(* Logix 5000 project; controller Test vendor 1 type 14 code 92 rev 33.11; software revision 33.00 *)

TASK MainTask (continuous, watchdog 500 ms) : MainProgram

MODULES
   Local : vendor 1 type 14 code 92 (ICP 0, rev 33.11)
      IN : vendor 1 type 7 code 1 (ICP 3, rev 3.2, Input RPI 20 ms)
      O : vendor 1 type 7 code 15 (ICP 2, rev 3.2, Output RPI 20 ms)
      Ethernet : 1756-ENBT (ICP 1, Ethernet 192.168.0.98, rev 6.4)
         IOLM1 : DXM (Ethernet 192.168.0.1, rev 2.22, StandardDataDriven RPI 20 ms)
END_MODULES

TYPE Banner_IOL_Device_SubIndex :
STRUCT
   Sub : DINT[34];
END_STRUCT
END_TYPE

TYPE Banner_IOL_Port_v5 :   // UDT that has all of the data items necessary to communicate with a specific Port on a IO-Link Master
STRUCT
   Port_Controlled : INT;   // Each bit represents a port on an IO-Link Master. Set to 1 to tell AOI to control that port.
   Port_Activate : INT;   // Each bit represents a port on an IO-Link Master. When ON that port will process any commands in queue.
   Port_Read : INT;   // Each bit represents a port on an IO-Link Master. Used to determine when device AOI has requested a Read command.
   Port_Write : INT;   // Each bit represents a port on an IO-Link Master. Used to determine when device AOI has requested a Write command.
   Port_RW_Complete : INT;   // Each bit represents a port on an IO-Link Master. Tells device AOI that Read or Write request has been completed.
   Port_Device_Read : INT;
   Data_Transfer : SINT[250];   // Array to transfer data from IO-Master to device AOIs.
END_STRUCT
END_TYPE

TYPE Banner_IOL_QM30VT3_Device :
STRUCT
   Initial_Global_Read : BOOL;
   Command : SINT;
   Data : Banner_IOL_QM30VT3_Device_Index;
   Reset : BOOL;
END_STRUCT
END_TYPE

TYPE Banner_IOL_QM30VT3_Device_Index :
STRUCT
   Index : Banner_IOL_Device_SubIndex[19];
   Metric_Config : Banner_IOL_QM30VT3_Metric_Config;
END_STRUCT
END_TYPE

TYPE Banner_IOL_QM30VT3_Metric_Config :
STRUCT
   Metric_1 : Banner_IOL_QM30VT3_Metric_Data;
   Metric_2 : Banner_IOL_QM30VT3_Metric_Data;
   Metric_3 : Banner_IOL_QM30VT3_Metric_Data;
   Metric_4 : Banner_IOL_QM30VT3_Metric_Data;
   Metric_5 : Banner_IOL_QM30VT3_Metric_Data;
   Metric_6 : Banner_IOL_QM30VT3_Metric_Data;
   Metric_7 : Banner_IOL_QM30VT3_Metric_Data;
   Num_of_Threshold_Samples : DINT;
END_STRUCT
END_TYPE

TYPE Banner_IOL_QM30VT3_Metric_Data :
STRUCT
   Metric : DINT;   // See IODD file for all options.
   Warning_Threshold : REAL;
   Alarm_Treshold : REAL;
END_STRUCT
END_TYPE

TYPE Banner_IOL_Rules :
STRUCT
   Byte_Pos : SINT;   // Byte Position to read from or write data to.
   Multi : SINT;   // Determines if a multiple byte length index is being accessed. Use 2 for 2 bytes length, 3 for 3 byte length, etc..
   Sub_Index : SINT;
   Signed : SINT;   // 0=Unsigned, 1=Signed
END_STRUCT
END_TYPE

TYPE Banner_IOL_Rules_Array :
STRUCT
   Length : DINT;
   Settings : Banner_IOL_Rules_SettingsArray[32];
END_STRUCT
END_TYPE

TYPE Banner_IOL_Rules_SettingsArray :
STRUCT
   Index : DINT;
   Num_Op : INT;   // Number of Operations to read/write Index.
   Total_Bytes : INT;
   RW : SINT;   // 0 = Read Only, 1 = Write Only, 2 = Read or Write
   Rules : Banner_IOL_Rules[34];   // Sub Index Position in IODD.
END_STRUCT
END_TYPE

TYPE Banner_IOLM_EL_v5 :   // Error Log for Messages to IOLM.
STRUCT
   RW : SINT;   // 0 = Read, 1 = Write.
   Port : SINT;   // Port number that generated error.
   Index : INT;   // IO-Link Index for generated error.
END_STRUCT
END_TYPE

TYPE Banner_IOLM_v5 :   // UDT to control IO-Link Masters.
STRUCT
   Message_Source_Data : SINT[260];
   Message_Destination_Data : SINT[260];
   Error_Log : Banner_IOLM_EL_v5[10];
   Error_Write_Retry : BOOL;
   Num_Error_MSGS : DINT;
   IO_Link_Master_Busy : BOOL;   // 0 = While waiting for a command, 1 = Processing command
   AOI_Reset : BOOL;
   Port_Data : Banner_IOL_Port_v5;   // All of the necessary data to work with the various ports of the IO-Link Master.
   Halt_Operation : BOOL;   // When parameter is 1 the AOI is halted as next available time frame.
   AOI_Halted : BOOL;   // AOI is in standby mode until Halt Operation tag is set back to 0.
END_STRUCT
END_TYPE

TYPE Banner_QM30VT3_FP_RMS_PD_v5 :
STRUCT
   X_RMS_Velocity : REAL;   // in/sec or mm/sec
   Y_RMS_Velocity : REAL;   // in/sec or mm/sec
   Z_RMS_Velocity : REAL;   // in/sec or mm/sec
   X_High_Freq_RMS_Accel : REAL;   // G
   Y_High_Freq_RMS_Accel : REAL;   // G
   Z_High_Freq_RMS_Accel : REAL;   // G
   Temperature : REAL;   // F or C
   X : Banner_QM30VT3_FP_RMS_XYZ_PD_v5;
   Y : Banner_QM30VT3_FP_RMS_XYZ_PD_v5;
   Z : Banner_QM30VT3_FP_RMS_XYZ_PD_v5;
   Temp_Warning : BOOL;
   Temp_Alarm : BOOL;
END_STRUCT
END_TYPE

TYPE Banner_QM30VT3_FP_RMS_XYZ_PD_v5 :
STRUCT
   Vel_Acute_Warning : BOOL;
   Vel_Acute_Alarm : BOOL;
   Vel_Chronic_Warning : BOOL;
   Vel_Chronic_Alarm : BOOL;
   HiFreq_Accel_Acute_Warning : BOOL;
   HiFreq_Accel_Acute_Alarm : BOOL;
   HiFreq_Accel_Chronic_Warning : BOOL;
   HiFreq_Accel_Chronic_Alarm : BOOL;
END_STRUCT
END_TYPE

TYPE Banner_QM30VT3_PDI_v5 :
STRUCT
   PD0_FP_imperial : Banner_QM30VT3_FP_RMS_PD_v5;
   PD1_SS_imperial : Banner_QM30VT3_SS_RMS_PD_v5;
   PD2_FP_metric : Banner_QM30VT3_FP_RMS_PD_v5;
   PD3_SS_metric : Banner_QM30VT3_SS_RMS_PD_v5;
   PD4_User_metric : Banner_QM30VT3_User_PD_v5;
   PD5_User_imperial : Banner_QM30VT3_User_PD_v5;
   DTI : SINT[32];
END_STRUCT
END_TYPE

TYPE Banner_QM30VT3_SS_RMS_PD_HiFreq_v5 :
STRUCT
   High_Frequency_RMS_Accel : DINT;
   Scale : INT;
   HiFreq_Accel_Acute_Warning : BOOL;
   HiFreq_Accel_Acute_Alarm : BOOL;
   HiFreq_Accel_Chronic_Warning : BOOL;
   HiFreq_Accel_Chronice_Alarm : BOOL;
END_STRUCT
END_TYPE

TYPE Banner_QM30VT3_SS_RMS_PD_v5 :
STRUCT
   X_Velocity : Banner_QM30VT3_SS_RMS_Vel_PD_v5;
   Y_Velocity : Banner_QM30VT3_SS_RMS_Vel_PD_v5;
   Z_Velocity : Banner_QM30VT3_SS_RMS_Vel_PD_v5;
   X_HiFreq : Banner_QM30VT3_SS_RMS_PD_HiFreq_v5;
   Y_HiFreq : Banner_QM30VT3_SS_RMS_PD_HiFreq_v5;
   Z_HiFreq : Banner_QM30VT3_SS_RMS_PD_HiFreq_v5;
   Temperature : DINT;   // F or C
   Scale : INT;
   Temp_Warning : BOOL;
   Temp_Alarm : BOOL;
END_STRUCT
END_TYPE

TYPE Banner_QM30VT3_SS_RMS_Vel_PD_v5 :
STRUCT
   RMS_Velocity : DINT;   // in/s or mm/sec
   Scale : INT;
   Vel_Acute_Warning : BOOL;
   Vel_Acute_Alarm : BOOL;
   Vel_Chronic_Warning : BOOL;
   Vel_Chronic_Alarm : BOOL;
END_STRUCT
END_TYPE

TYPE Banner_QM30VT3_User_PD_v5 :
STRUCT
   Metric : REAL[8];
   M1_Chan_1_Warning : BOOL;
   M1_Chan_2_Alarm : BOOL;
   M2_Chan_1_Warning : BOOL;
   M2_Chan_2_Alarm : BOOL;
   M3_Chan_1_Warning : BOOL;
   M3_Chan_2_Alarm : BOOL;
   M4_Chan_1_Warning : BOOL;
   M4_Chan_2_Alarm : BOOL;
   M5_Chan_1_Warning : BOOL;
   M5_Chan_2_Alarm : BOOL;
   M6_Chan_1_Warning : BOOL;
   M6_Chan_2_Alarm : BOOL;
   M7_Chan_1_Warning : BOOL;
   M7_Chan_2_Alarm : BOOL;
END_STRUCT
END_TYPE

ADD_ON_INSTRUCTION Banner_DXMR_IOLM_Param_v5   (* revision 5.0, vendor Banner Engineering *)
// AOI that controls a Banner IO-Link Master with IO-Link Devices
// Revision note:
// Added Port Control functionality. This should simplify the setup. Also added links for direct connection to the Input and Output Assmebly Instances.
VAR_IN_OUT
   IOLM : Banner_IOLM_v5; {required}
   Input : SINT[456]; {required}
   Output : SINT[456]; {required}
END_VAR
VAR_INPUT
   Port1 : BOOL; {required}
   Port2 : BOOL; {required}
   Port3 : BOOL; {required}
   Port4 : BOOL; {required}
   Port5 : BOOL; {required}
   Port6 : BOOL; {required}
   Port7 : BOOL; {required}
   Port8 : BOOL; {required}
END_VAR
VAR_OUTPUT
   Done : BOOL; {visible}
   Busy : BOOL; {visible}
   Error : BOOL; {visible}
END_VAR
VAR
   Lock : DINT; {access None}
   Byte_Length : SINT; {access None}
   Current_Port : INT; {access None}   // Current port to communicate with via the IO-Link Master.
   Timer : TIMER := (PRE := 500); {access None}
   Error_Index : DINT; {access None}
   Timer2 : TIMER := (PRE := 5000); {access None}
   Temp_Index : INT; {access None}
   ErrCount : DINT; {access None}
   Timer4 : TIMER := (PRE := 2000); {access None}
   Timer5 : TIMER := (PRE := 2000); {access None}
   Timer3 : TIMER := (PRE := 2000); {access None}
   Timer6 : TIMER := (PRE := 3000); {access None}
   Timer7 : TIMER := (PRE := 3000); {access None}
   Timer8 : TIMER := (PRE := 3000); {access None}
   Write_Index : DINT; {access None}
   WriteTimer : TIMER := (PRE := 60000); {access None}
   WriteCnt : DINT; {access None}
   Last_Index : DINT; {access None}
   WrCntTotal : DINT; {access None}
END_VAR

ROUTINE Logic   (* ladder *)
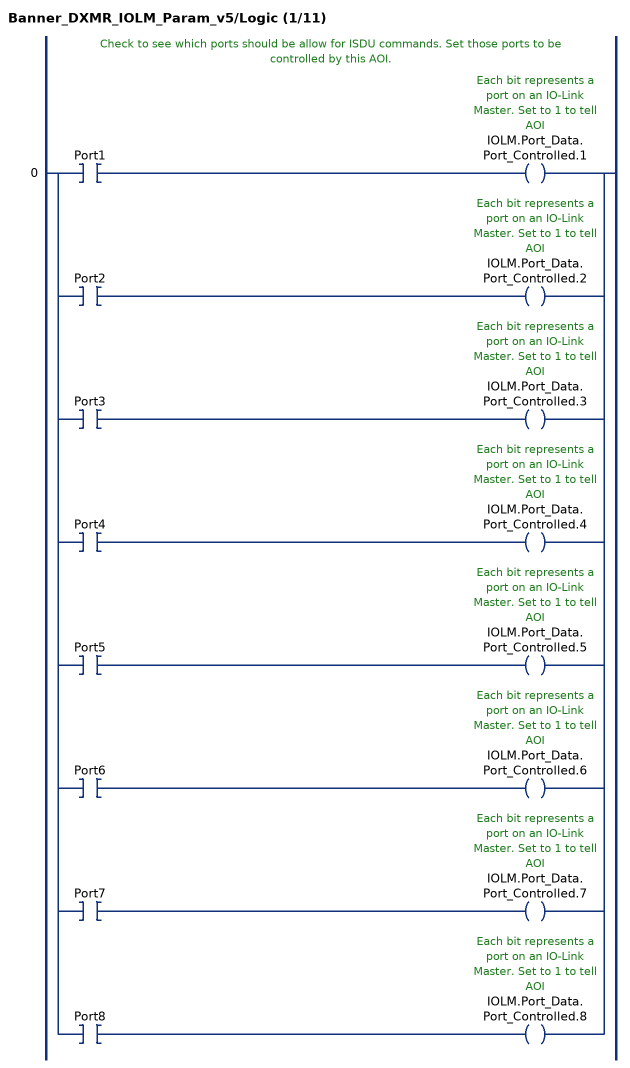
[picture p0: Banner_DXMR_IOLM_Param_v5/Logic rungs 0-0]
   // Check to see which ports should be allow for ISDU commands. Set those ports to be controlled by this AOI.
   0: [XIC(Port1) OTE(IOLM.Port_Data.Port_Controlled.1) ,XIC(Port2) OTE(IOLM.Port_Data.Port_Controlled.2) ,XIC(Port3) OTE(IOLM.Port_Data.Port_Controlled.3) ,XIC(Port4) OTE(IOLM.Port_Data.Port_Controlled.4) ,XIC(Port5) OTE(IOLM.Port_Data.Port_Controlled.5) ,XIC(Port6) OTE(IOLM.Port_Data.Port_Controlled.6) ,XIC(Port7) OTE(IOLM.Port_Data.Port_Controlled.7) ,XIC(Port8) OTE(IOLM.Port_Data.Port_Controlled.8) ];
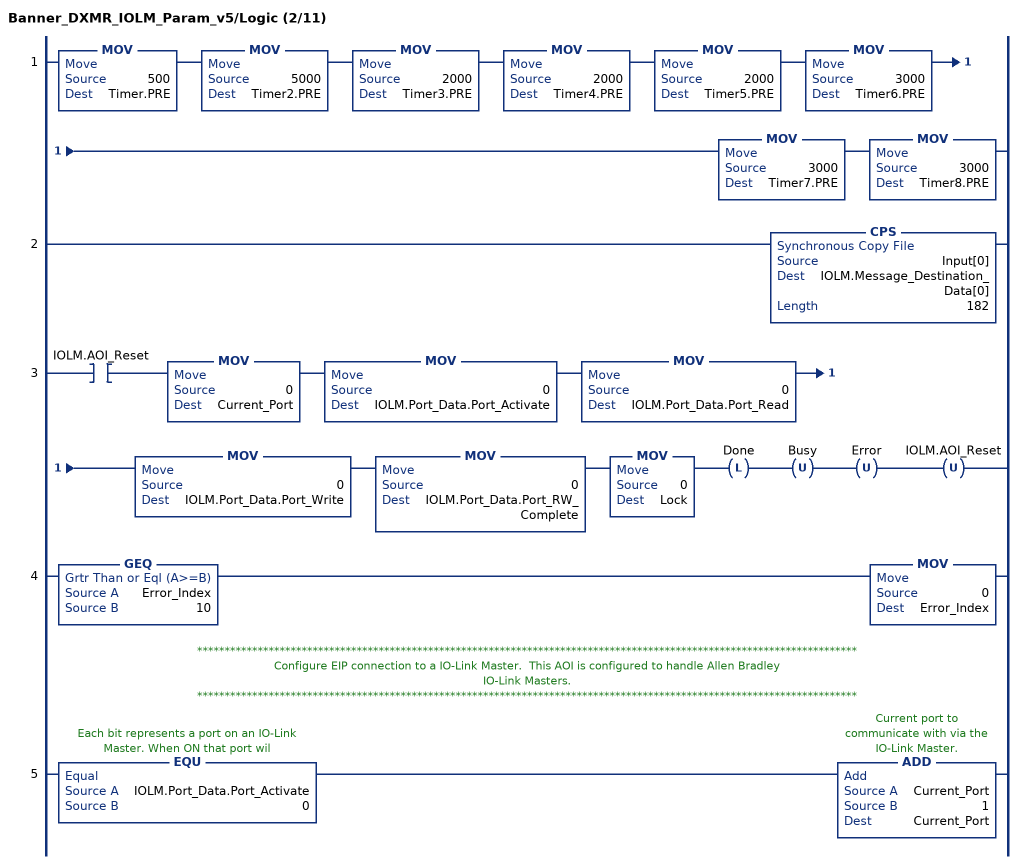
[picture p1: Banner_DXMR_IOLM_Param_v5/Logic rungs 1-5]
   1: MOV(500,Timer.PRE)MOV(5000,Timer2.PRE)MOV(2000,Timer3.PRE)MOV(2000,Timer4.PRE)MOV(2000,Timer5.PRE)MOV(3000,Timer6.PRE)MOV(3000,Timer7.PRE)MOV(3000,Timer8.PRE);
   2: CPS(Input[0],IOLM.Message_Destination_Data[0],182);
   3: XIC(IOLM.AOI_Reset)MOV(0,Current_Port)MOV(0,IOLM.Port_Data.Port_Activate)MOV(0,IOLM.Port_Data.Port_Read)MOV(0,IOLM.Port_Data.Port_Write)MOV(0,IOLM.Port_Data.Port_RW_Complete)MOV(0,Lock)OTL(Done)OTU(Busy)OTU(Error)OTU(IOLM.AOI_Reset);
   4: GEQ(Error_Index,10)MOV(0,Error_Index);
   // ************************************************************************************************************************
   // Configure EIP connection to a IO-Link Master.  This AOI is configured to handle Allen Bradley
   // IO-Link Masters.
   // ************************************************************************************************************************
   5: EQU(IOLM.Port_Data.Port_Activate,0)ADD(Current_Port,1,Current_Port);
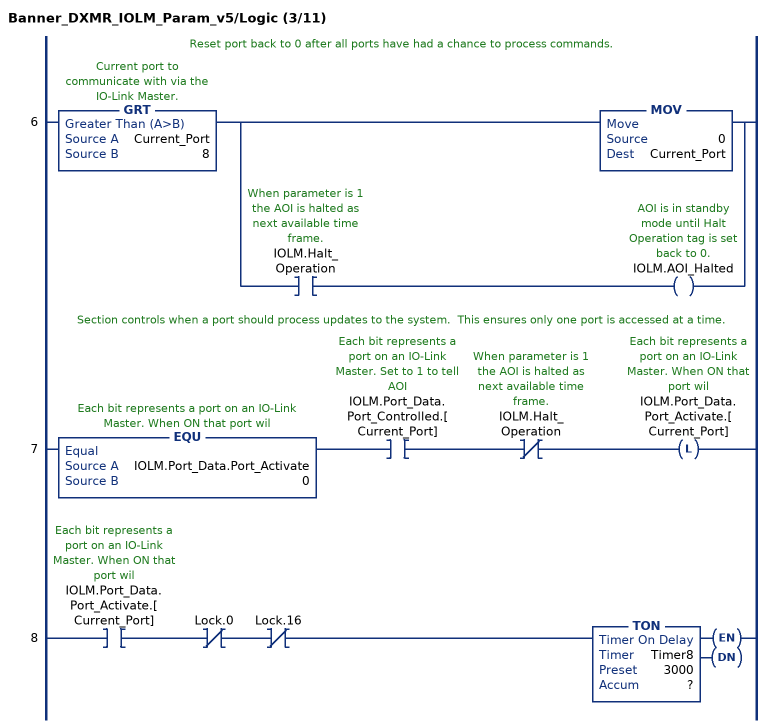
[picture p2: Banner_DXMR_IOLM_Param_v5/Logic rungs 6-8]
   // Reset port back to 0 after all ports have had a chance to process commands.
   6: GRT(Current_Port,8)[MOV(0,Current_Port) ,XIC(IOLM.Halt_Operation) OTE(IOLM.AOI_Halted) ];
   // Section controls when a port should process updates to the system.  This ensures only one port is accessed at a time.
   7: EQU(IOLM.Port_Data.Port_Activate,0)XIC(IOLM.Port_Data.Port_Controlled.[Current_Port])XIO(IOLM.Halt_Operation)OTL(IOLM.Port_Data.Port_Activate.[Current_Port]);
   8: XIC(IOLM.Port_Data.Port_Activate.[Current_Port])XIO(Lock.0)XIO(Lock.16)TON(Timer8,?,?);
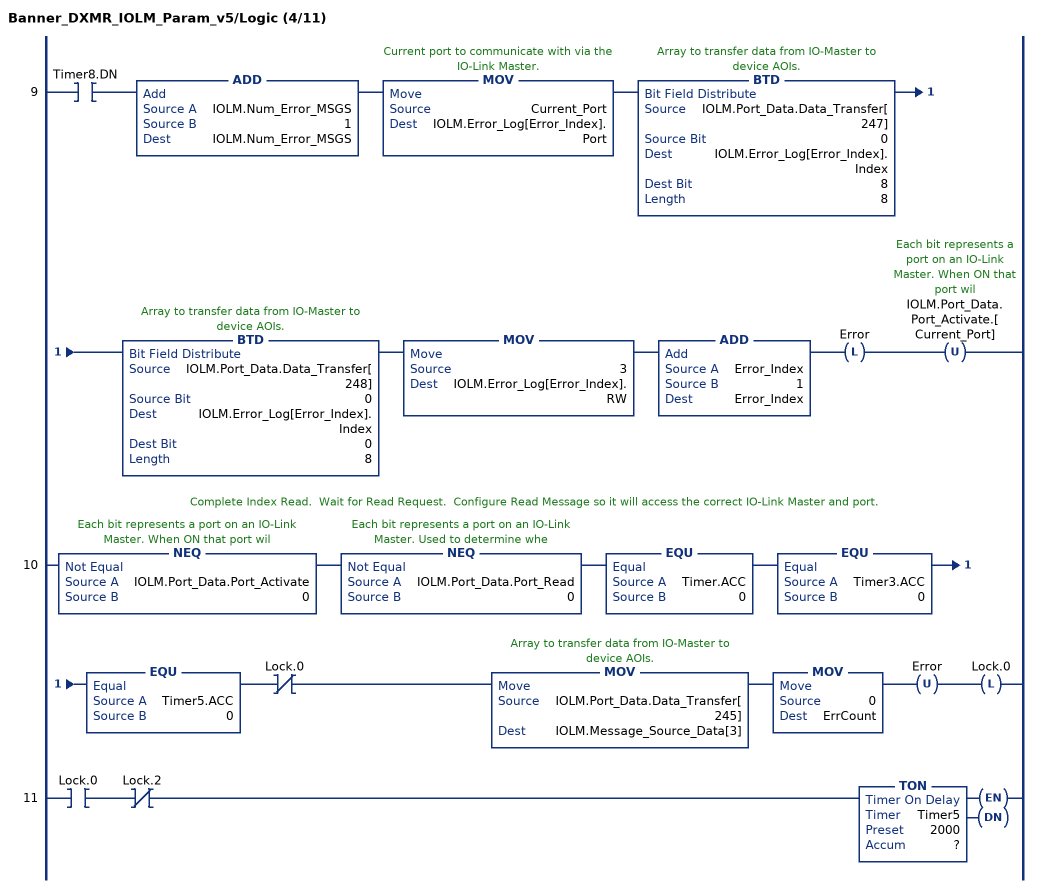
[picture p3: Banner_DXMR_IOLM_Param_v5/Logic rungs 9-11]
   9: XIC(Timer8.DN)ADD(IOLM.Num_Error_MSGS,1,IOLM.Num_Error_MSGS)MOV(Current_Port,IOLM.Error_Log[Error_Index].Port)BTD(IOLM.Port_Data.Data_Transfer[247],0,IOLM.Error_Log[Error_Index].Index,8,8)BTD(IOLM.Port_Data.Data_Transfer[248],0,IOLM.Error_Log[Error_Index].Index,0,8)MOV(3,IOLM.Error_Log[Error_Index].RW)ADD(Error_Index,1,Error_Index)OTL(Error)OTU(IOLM.Port_Data.Port_Activate.[Current_Port]);
   // Complete Index Read.  Wait for Read Request.  Configure Read Message so it will access the correct IO-Link Master and port.
   10: NEQ(IOLM.Port_Data.Port_Activate,0)NEQ(IOLM.Port_Data.Port_Read,0)EQU(Timer.ACC,0)EQU(Timer3.ACC,0)EQU(Timer5.ACC,0)XIO(Lock.0)MOV(IOLM.Port_Data.Data_Transfer[245],IOLM.Message_Source_Data[3])MOV(0,ErrCount)OTU(Error)OTL(Lock.0);
   11: XIC(Lock.0)XIO(Lock.2)TON(Timer5,?,?);
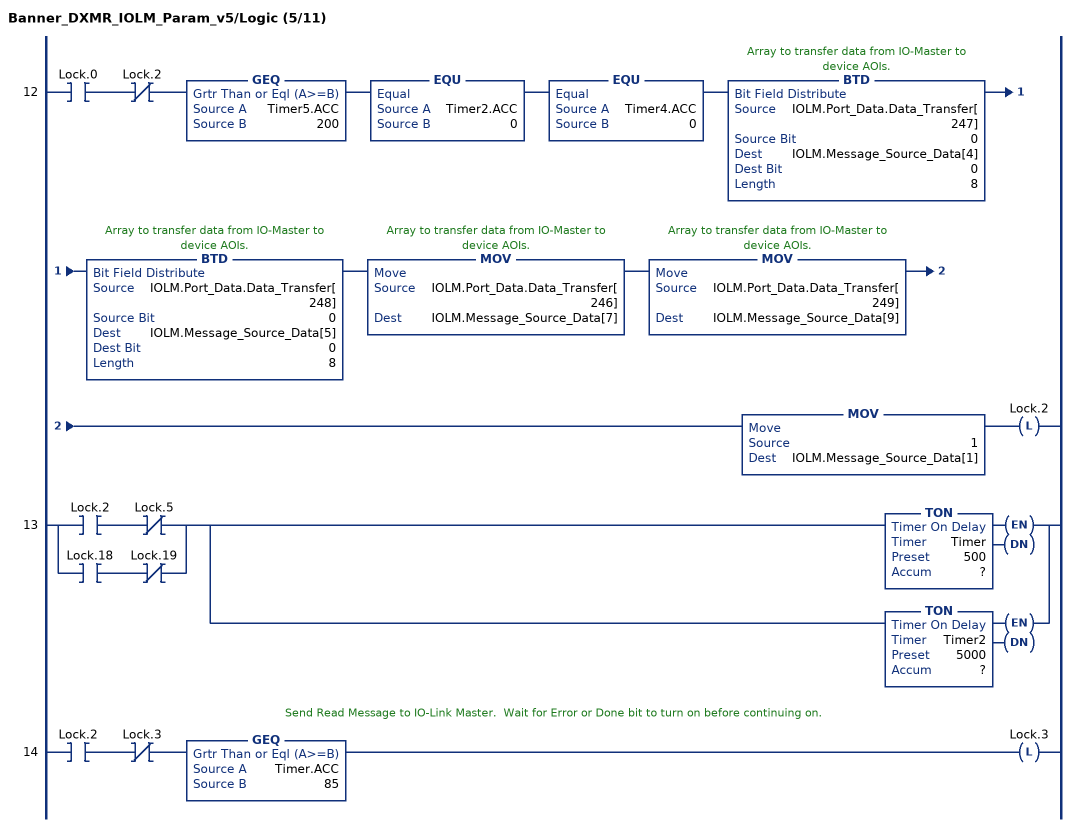
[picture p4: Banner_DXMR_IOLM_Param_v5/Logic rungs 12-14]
   12: XIC(Lock.0)XIO(Lock.2)GEQ(Timer5.ACC,200)EQU(Timer2.ACC,0)EQU(Timer4.ACC,0)BTD(IOLM.Port_Data.Data_Transfer[247],0,IOLM.Message_Source_Data[4],0,8)BTD(IOLM.Port_Data.Data_Transfer[248],0,IOLM.Message_Source_Data[5],0,8)MOV(IOLM.Port_Data.Data_Transfer[246],IOLM.Message_Source_Data[7])MOV(IOLM.Port_Data.Data_Transfer[249],IOLM.Message_Source_Data[9])MOV(1,IOLM.Message_Source_Data[1])OTL(Lock.2);
   13: [XIC(Lock.2) XIO(Lock.5) ,XIC(Lock.18) XIO(Lock.19) ][TON(Timer,?,?) ,TON(Timer2,?,?) ];
   // Send Read Message to IO-Link Master.  Wait for Error or Done bit to turn on before continuing on.
   14: XIC(Lock.2)XIO(Lock.3)GEQ(Timer.ACC,85)OTL(Lock.3);
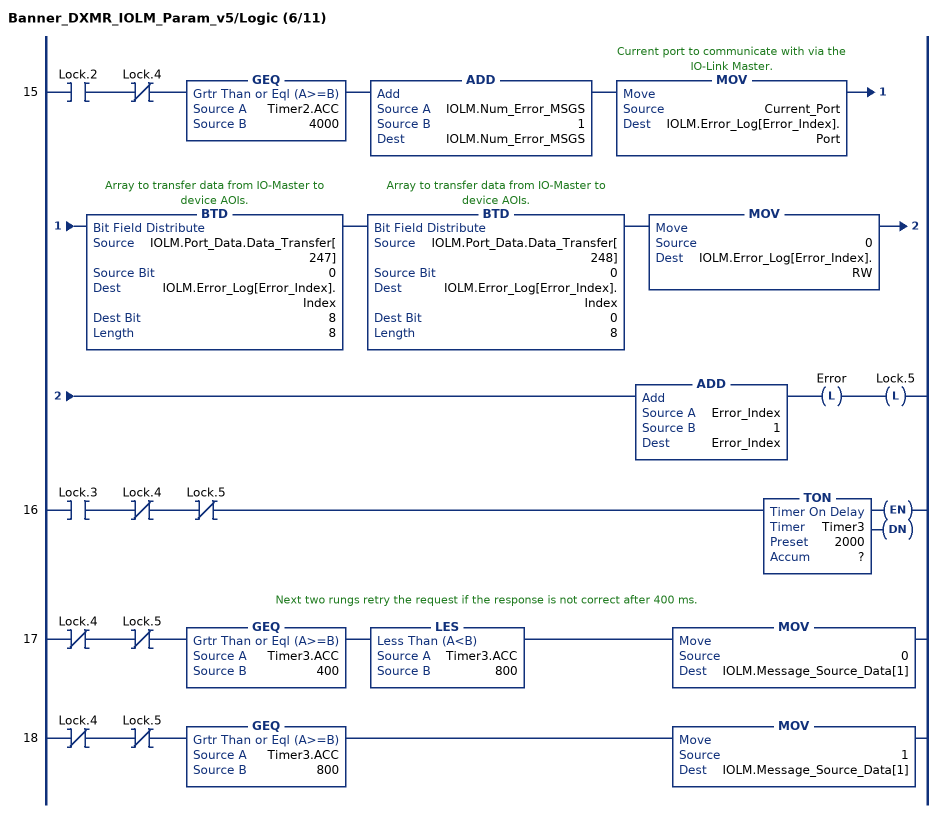
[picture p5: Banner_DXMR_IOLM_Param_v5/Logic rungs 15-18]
   15: XIC(Lock.2)XIO(Lock.4)GEQ(Timer2.ACC,4000)ADD(IOLM.Num_Error_MSGS,1,IOLM.Num_Error_MSGS)MOV(Current_Port,IOLM.Error_Log[Error_Index].Port)BTD(IOLM.Port_Data.Data_Transfer[247],0,IOLM.Error_Log[Error_Index].Index,8,8)BTD(IOLM.Port_Data.Data_Transfer[248],0,IOLM.Error_Log[Error_Index].Index,0,8)MOV(0,IOLM.Error_Log[Error_Index].RW)ADD(Error_Index,1,Error_Index)OTL(Error)OTL(Lock.5);
   16: XIC(Lock.3)XIO(Lock.4)XIO(Lock.5)TON(Timer3,?,?);
   // Next two rungs retry the request if the response is not correct after 400 ms.
   17: XIO(Lock.4)XIO(Lock.5)GEQ(Timer3.ACC,400)LES(Timer3.ACC,800)MOV(0,IOLM.Message_Source_Data[1]);
   18: XIO(Lock.4)XIO(Lock.5)GEQ(Timer3.ACC,800)MOV(1,IOLM.Message_Source_Data[1]);
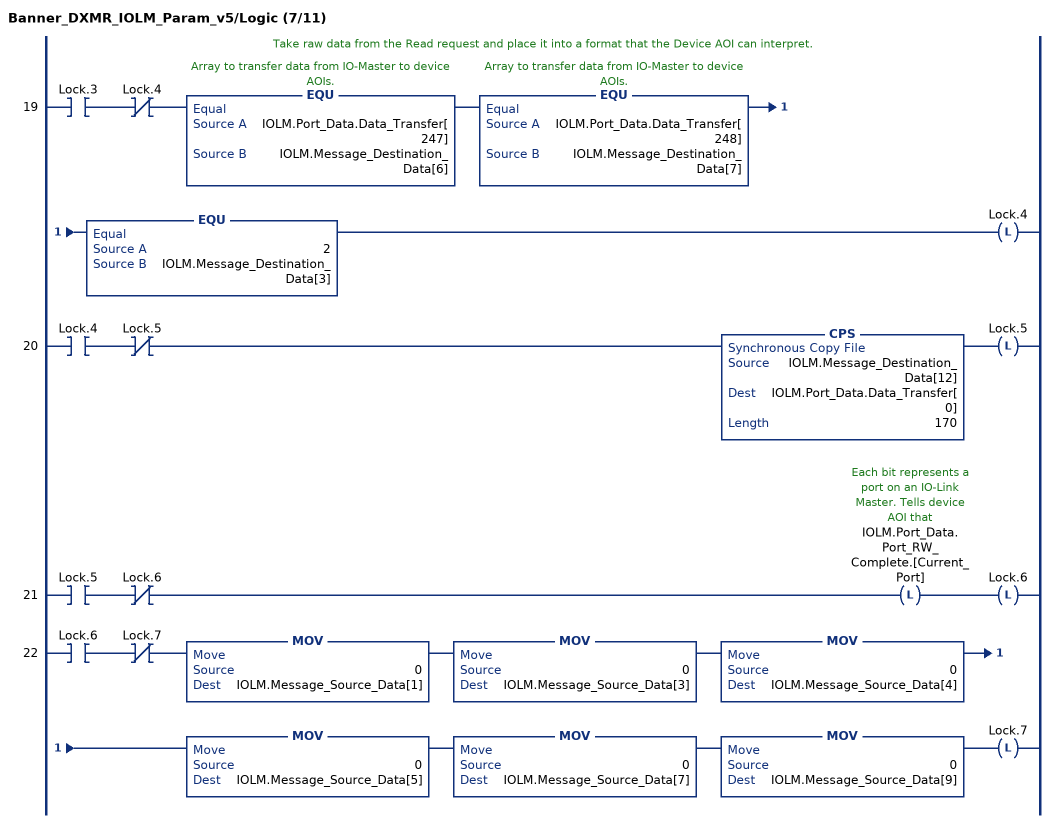
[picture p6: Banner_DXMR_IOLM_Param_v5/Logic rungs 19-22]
   // Take raw data from the Read request and place it into a format that the Device AOI can interpret.
   19: XIC(Lock.3)XIO(Lock.4)EQU(IOLM.Port_Data.Data_Transfer[247],IOLM.Message_Destination_Data[6])EQU(IOLM.Port_Data.Data_Transfer[248],IOLM.Message_Destination_Data[7])EQU(2,IOLM.Message_Destination_Data[3])OTL(Lock.4);
   20: XIC(Lock.4)XIO(Lock.5)CPS(IOLM.Message_Destination_Data[12],IOLM.Port_Data.Data_Transfer[0],170)OTL(Lock.5);
   21: XIC(Lock.5)XIO(Lock.6)OTL(IOLM.Port_Data.Port_RW_Complete.[Current_Port])OTL(Lock.6);
   22: XIC(Lock.6)XIO(Lock.7)MOV(0,IOLM.Message_Source_Data[1])MOV(0,IOLM.Message_Source_Data[3])MOV(0,IOLM.Message_Source_Data[4])MOV(0,IOLM.Message_Source_Data[5])MOV(0,IOLM.Message_Source_Data[7])MOV(0,IOLM.Message_Source_Data[9])OTL(Lock.7);
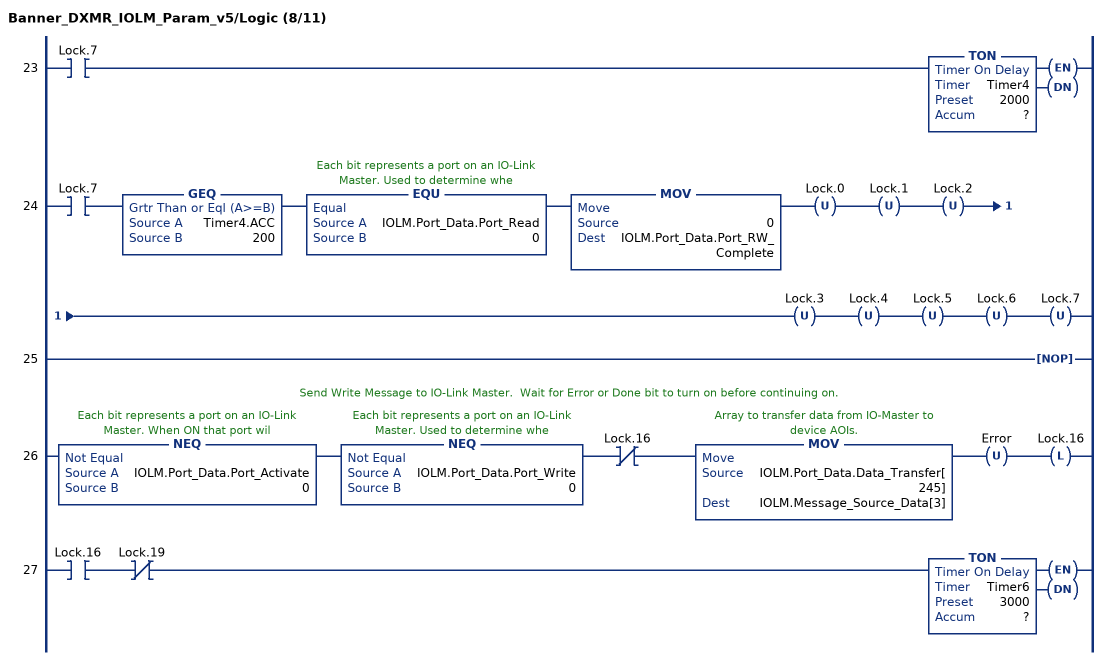
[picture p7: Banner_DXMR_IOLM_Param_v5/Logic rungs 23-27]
   23: XIC(Lock.7)TON(Timer4,?,?);
   24: XIC(Lock.7)GEQ(Timer4.ACC,200)EQU(IOLM.Port_Data.Port_Read,0)MOV(0,IOLM.Port_Data.Port_RW_Complete)OTU(Lock.0)OTU(Lock.1)OTU(Lock.2)OTU(Lock.3)OTU(Lock.4)OTU(Lock.5)OTU(Lock.6)OTU(Lock.7);
   25: NOP();
   // Send Write Message to IO-Link Master.  Wait for Error or Done bit to turn on before continuing on.
   26: NEQ(IOLM.Port_Data.Port_Activate,0)NEQ(IOLM.Port_Data.Port_Write,0)XIO(Lock.16)MOV(IOLM.Port_Data.Data_Transfer[245],IOLM.Message_Source_Data[3])OTU(Error)OTL(Lock.16);
   27: XIC(Lock.16)XIO(Lock.19)TON(Timer6,?,?);
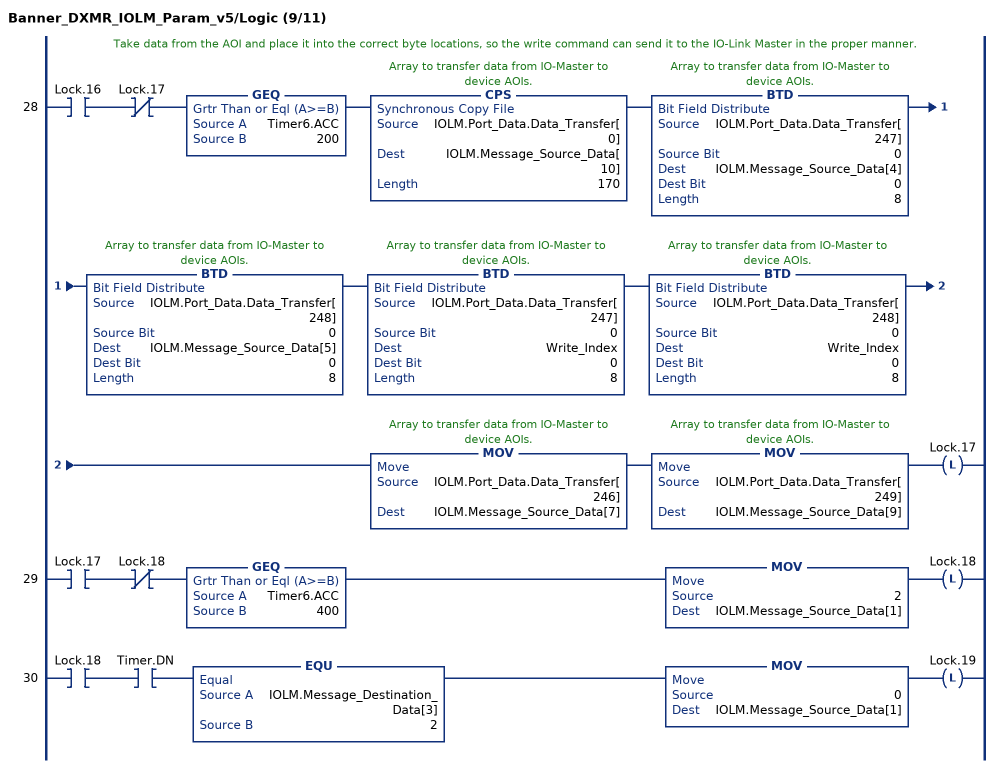
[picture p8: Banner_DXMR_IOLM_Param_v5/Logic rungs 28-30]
   // Take data from the AOI and place it into the correct byte locations, so the write command can send it to the IO-Link Master in the proper manner.
   28: XIC(Lock.16)XIO(Lock.17)GEQ(Timer6.ACC,200)CPS(IOLM.Port_Data.Data_Transfer[0],IOLM.Message_Source_Data[10],170)BTD(IOLM.Port_Data.Data_Transfer[247],0,IOLM.Message_Source_Data[4],0,8)BTD(IOLM.Port_Data.Data_Transfer[248],0,IOLM.Message_Source_Data[5],0,8)BTD(IOLM.Port_Data.Data_Transfer[247],0,Write_Index,0,8)BTD(IOLM.Port_Data.Data_Transfer[248],0,Write_Index,0,8)MOV(IOLM.Port_Data.Data_Transfer[246],IOLM.Message_Source_Data[7])MOV(IOLM.Port_Data.Data_Transfer[249],IOLM.Message_Source_Data[9])OTL(Lock.17);
   29: XIC(Lock.17)XIO(Lock.18)GEQ(Timer6.ACC,400)MOV(2,IOLM.Message_Source_Data[1])OTL(Lock.18);
   30: XIC(Lock.18)XIC(Timer.DN)EQU(IOLM.Message_Destination_Data[3],2)MOV(0,IOLM.Message_Source_Data[1])OTL(Lock.19);
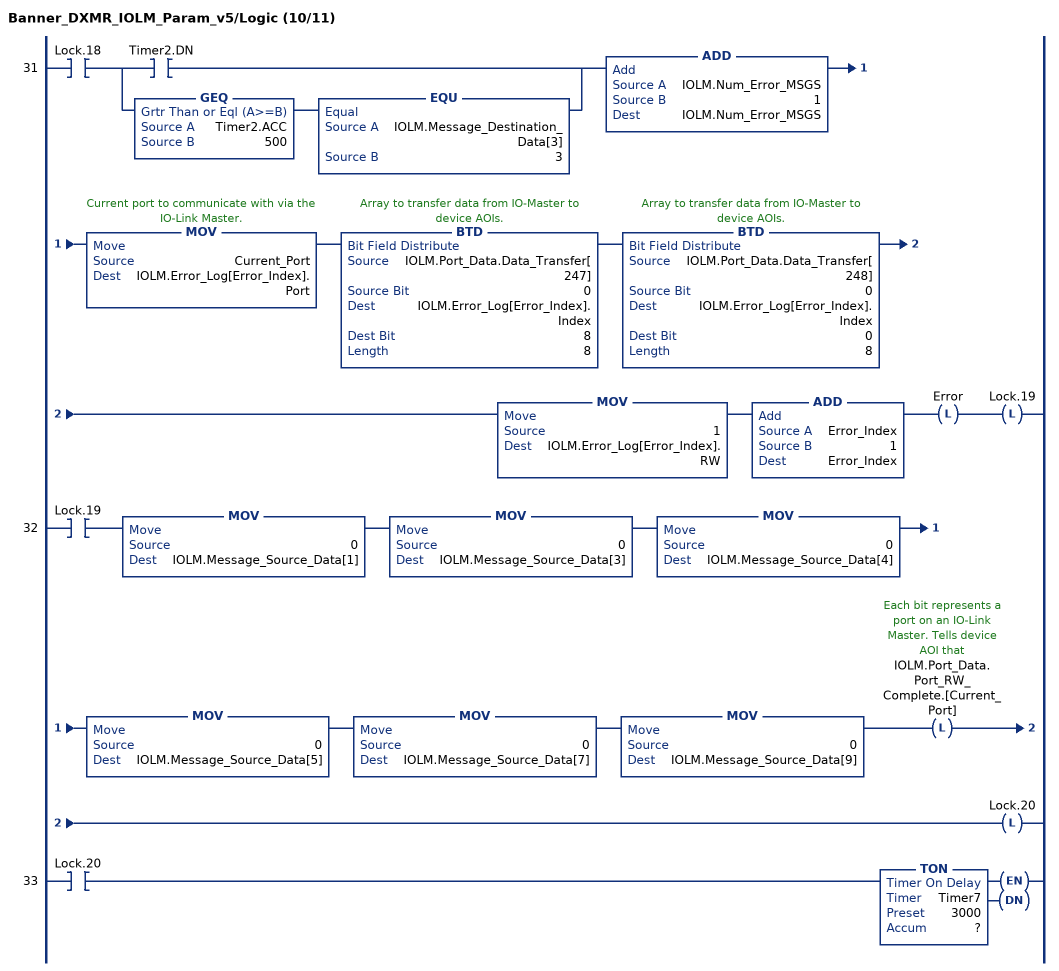
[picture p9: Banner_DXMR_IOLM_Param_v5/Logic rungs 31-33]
   31: XIC(Lock.18)[XIC(Timer2.DN) ,GEQ(Timer2.ACC,500) EQU(IOLM.Message_Destination_Data[3],3) ]ADD(IOLM.Num_Error_MSGS,1,IOLM.Num_Error_MSGS)MOV(Current_Port,IOLM.Error_Log[Error_Index].Port)BTD(IOLM.Port_Data.Data_Transfer[247],0,IOLM.Error_Log[Error_Index].Index,8,8)BTD(IOLM.Port_Data.Data_Transfer[248],0,IOLM.Error_Log[Error_Index].Index,0,8)MOV(1,IOLM.Error_Log[Error_Index].RW)ADD(Error_Index,1,Error_Index)OTL(Error)OTL(Lock.19);
   32: XIC(Lock.19)MOV(0,IOLM.Message_Source_Data[1])MOV(0,IOLM.Message_Source_Data[3])MOV(0,IOLM.Message_Source_Data[4])MOV(0,IOLM.Message_Source_Data[5])MOV(0,IOLM.Message_Source_Data[7])MOV(0,IOLM.Message_Source_Data[9])OTL(IOLM.Port_Data.Port_RW_Complete.[Current_Port])OTL(Lock.20);
   33: XIC(Lock.20)TON(Timer7,?,?);
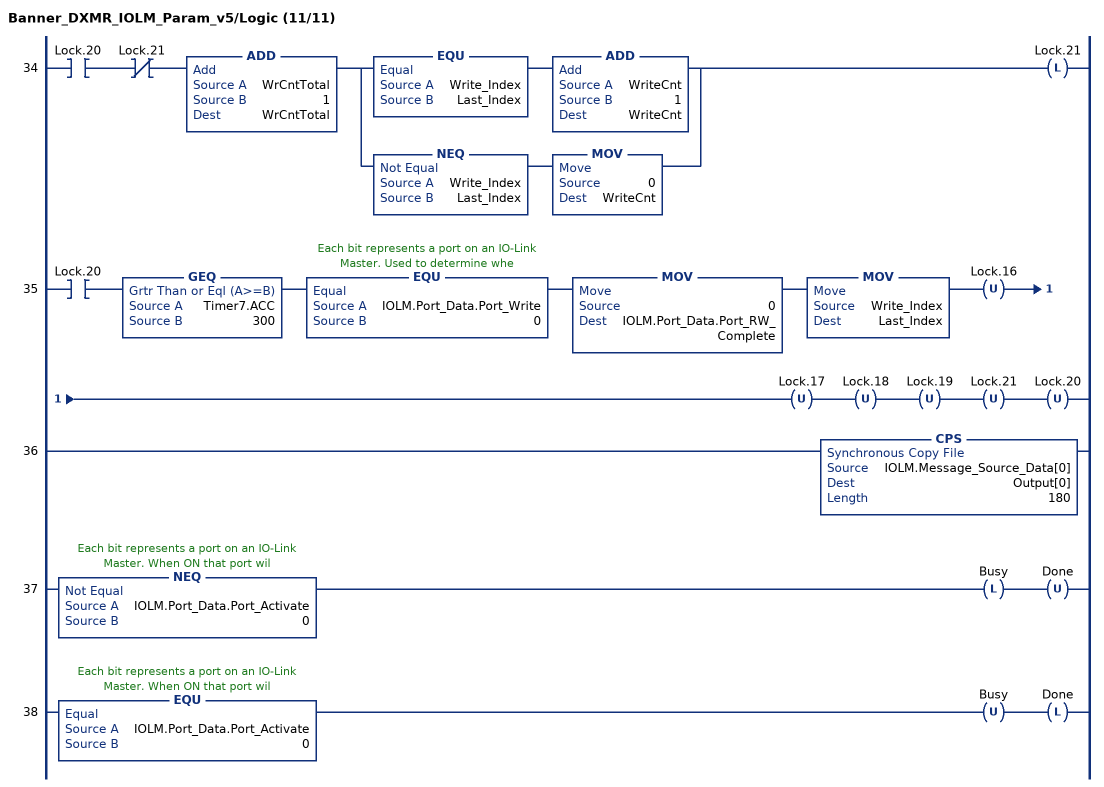
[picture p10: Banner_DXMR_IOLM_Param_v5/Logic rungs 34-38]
   34: XIC(Lock.20)XIO(Lock.21)ADD(WrCntTotal,1,WrCntTotal)[EQU(Write_Index,Last_Index) ADD(WriteCnt,1,WriteCnt) ,NEQ(Write_Index,Last_Index) MOV(0,WriteCnt) ]OTL(Lock.21);
   35: XIC(Lock.20)GEQ(Timer7.ACC,300)EQU(IOLM.Port_Data.Port_Write,0)MOV(0,IOLM.Port_Data.Port_RW_Complete)MOV(Write_Index,Last_Index)OTU(Lock.16)OTU(Lock.17)OTU(Lock.18)OTU(Lock.19)OTU(Lock.21)OTU(Lock.20);
   36: CPS(IOLM.Message_Source_Data[0],Output[0],180);
   37: NEQ(IOLM.Port_Data.Port_Activate,0)OTL(Busy)OTU(Done);
   38: EQU(IOLM.Port_Data.Port_Activate,0)OTU(Busy)OTL(Done);
END_ROUTINE
END_ADD_ON_INSTRUCTION

ADD_ON_INSTRUCTION Banner_IOL_QM30VT3_Parameter_v5   (* revision 5.0 *)
// AOI that reads and writes to an IO-Link devices parameter data.
VAR_IN_OUT
   Device : Banner_IOL_QM30VT3_Device; {required}
   Rules : Banner_IOL_Rules_Array; {required}
   Port_Data : Banner_IOL_Port_v5; {required}
END_VAR
VAR_INPUT
   Port : DINT; {required}
END_VAR
VAR_OUTPUT
   Done : BOOL; {access Read Only, visible}
   Busy : BOOL; {access Read Only, visible}
END_VAR
VAR
   Control : DINT; {access None}
   Inprocess_Index : INT; {access None}
   Index_Write_Inprocess : INT; {access None}
   Index_Write_Control : INT; {access None}
   Global_Read_Command : INT; {access None}
   Command_Being_Processed : BOOL; {access None}
   r_dex2 : INT; {access None}
   r_dex1 : INT; {access None}
   g_index : INT; {access None}
   r_dex3 : INT; {access None}
   r_dex4 : INT; {access None}
   r_dex5 : INT; {access None}
   Wr_Upper : INT; {access None}
   w_dex5 : INT; {access None}
   w_dex4 : INT; {access None}
   w_dex3 : INT; {access None}
   w_dex2 : INT; {access None}
   w_dex1 : INT; {access None}
   m3 : INT; {access None}
   m2 : INT; {access None}
   m1 : INT; {access None}
   s_dex : INT; {access None}
   GlobalCon : DINT; {access None}
   b_dex : INT; {access None}
   Temp_Int : INT; {access None}
END_VAR

ROUTINE Logic   (* ladder *)
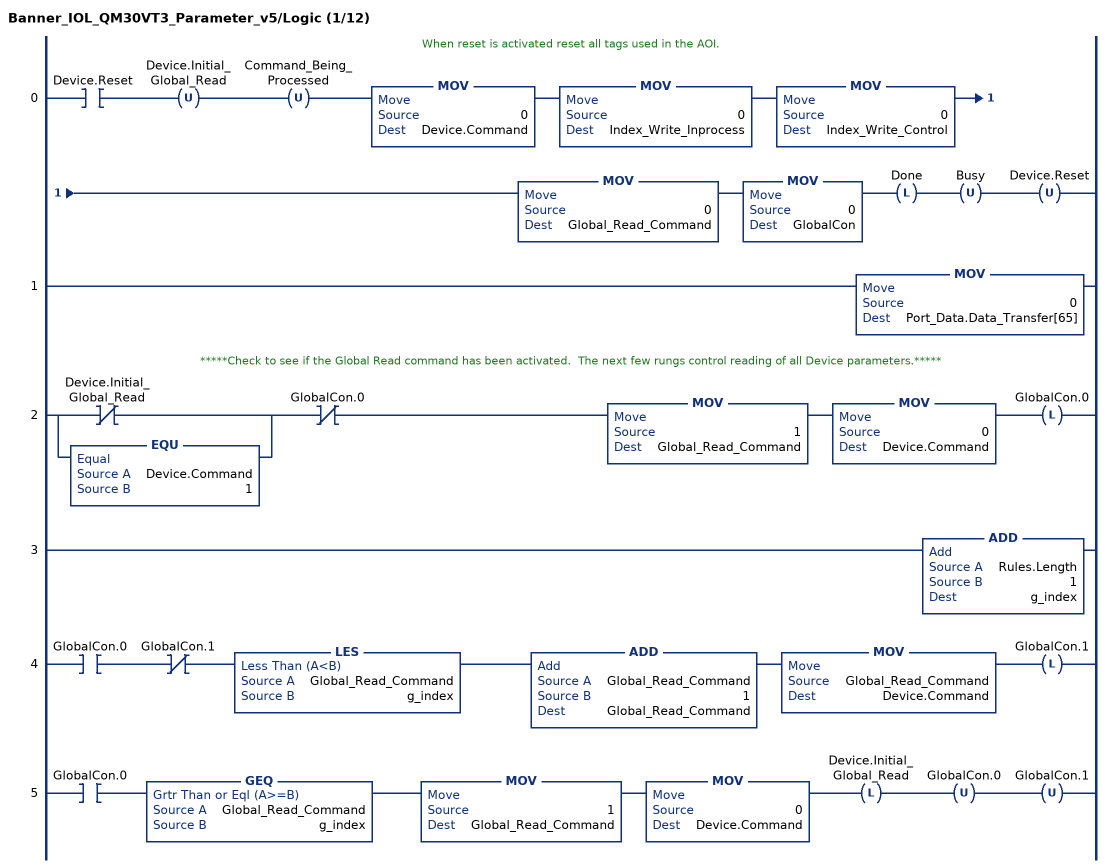
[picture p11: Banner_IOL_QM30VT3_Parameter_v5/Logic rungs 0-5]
   // When reset is activated reset all tags used in the AOI.
   0: XIC(Device.Reset)OTU(Device.Initial_Global_Read)OTU(Command_Being_Processed)MOV(0,Device.Command)MOV(0,Index_Write_Inprocess)MOV(0,Index_Write_Control)MOV(0,Global_Read_Command)MOV(0,GlobalCon)OTL(Done)OTU(Busy)OTU(Device.Reset);
   1: MOV(0,Port_Data.Data_Transfer[65]);
   // *****Check to see if the Global Read command has been activated.  The next few rungs control reading of all Device parameters.*****
   2: [XIO(Device.Initial_Global_Read) ,EQU(Device.Command,1) ]XIO(GlobalCon.0)MOV(1,Global_Read_Command)MOV(0,Device.Command)OTL(GlobalCon.0);
   3: ADD(Rules.Length,1,g_index);
   4: XIC(GlobalCon.0)XIO(GlobalCon.1)LES(Global_Read_Command,g_index)ADD(Global_Read_Command,1,Global_Read_Command)MOV(Global_Read_Command,Device.Command)OTL(GlobalCon.1);
   5: XIC(GlobalCon.0)GEQ(Global_Read_Command,g_index)MOV(1,Global_Read_Command)MOV(0,Device.Command)OTL(Device.Initial_Global_Read)OTU(GlobalCon.0)OTU(GlobalCon.1);
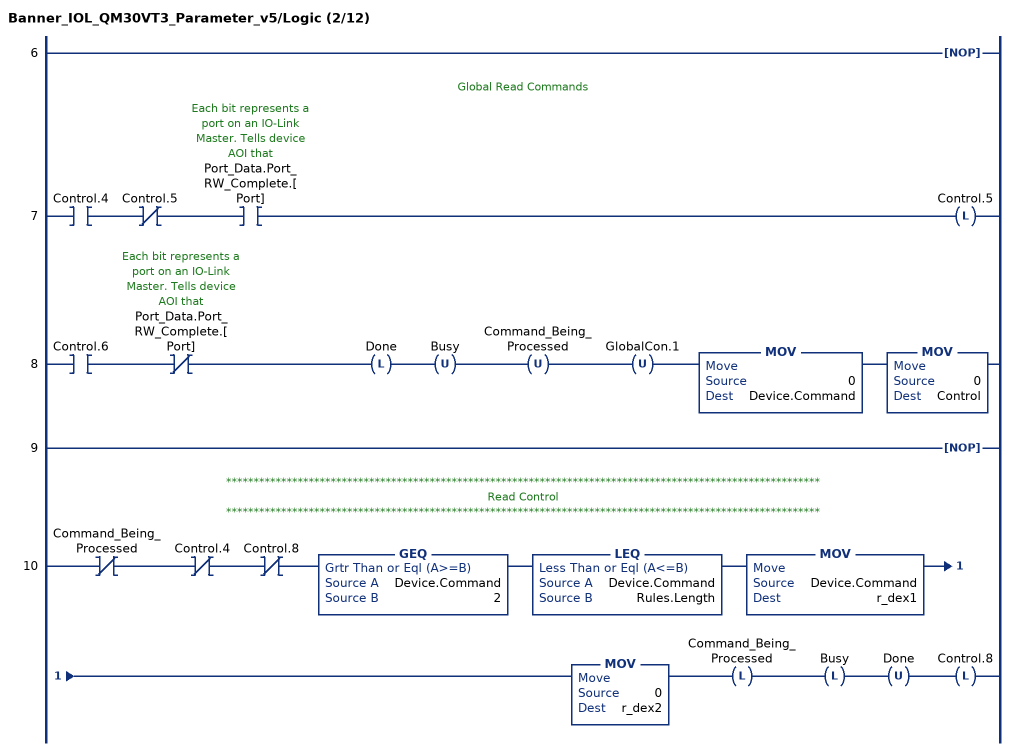
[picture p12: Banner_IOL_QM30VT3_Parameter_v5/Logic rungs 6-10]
   6: NOP();
   // Global Read Commands
   7: XIC(Control.4)XIO(Control.5)XIC(Port_Data.Port_RW_Complete.[Port])OTL(Control.5);
   8: XIC(Control.6)XIO(Port_Data.Port_RW_Complete.[Port])OTL(Done)OTU(Busy)OTU(Command_Being_Processed)OTU(GlobalCon.1)MOV(0,Device.Command)MOV(0,Control);
   9: NOP();
   // ************************************************************************************************************
   // Read Control
   // ************************************************************************************************************
   10: XIO(Command_Being_Processed)XIO(Control.4)XIO(Control.8)GEQ(Device.Command,2)LEQ(Device.Command,Rules.Length)MOV(Device.Command,r_dex1)MOV(0,r_dex2)OTL(Command_Being_Processed)OTL(Busy)OTU(Done)OTL(Control.8);
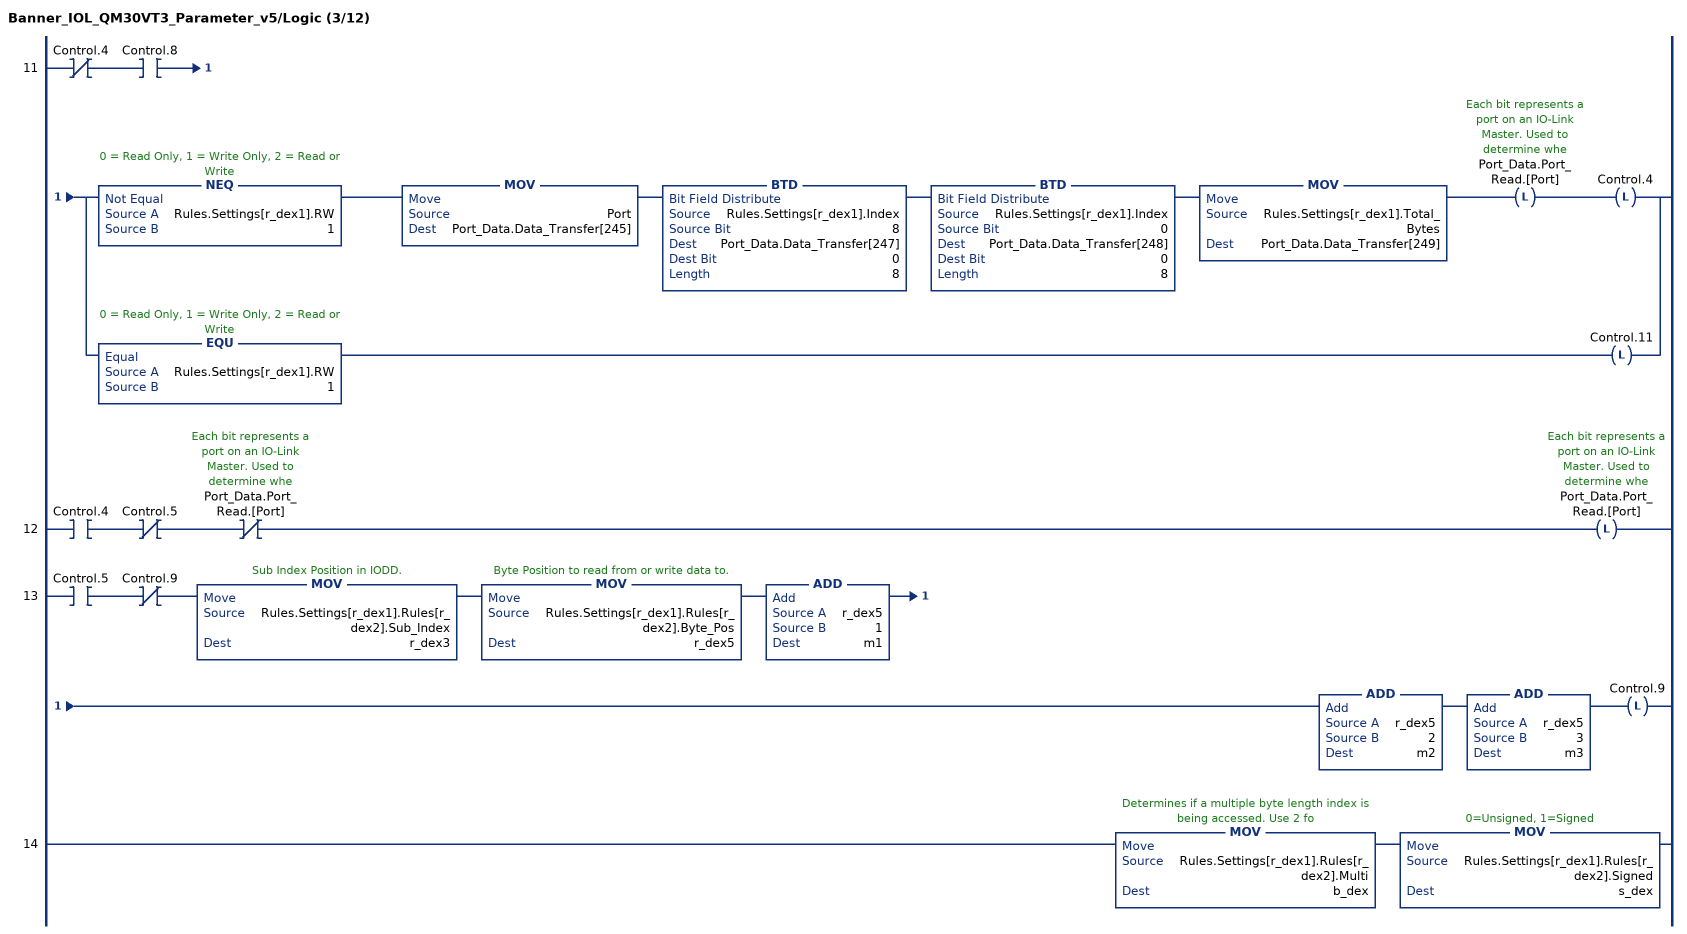
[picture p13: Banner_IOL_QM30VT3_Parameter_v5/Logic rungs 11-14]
   11: XIO(Control.4)XIC(Control.8)[NEQ(Rules.Settings[r_dex1].RW,1) MOV(Port,Port_Data.Data_Transfer[245]) BTD(Rules.Settings[r_dex1].Index,8,Port_Data.Data_Transfer[247],0,8) BTD(Rules.Settings[r_dex1].Index,0,Port_Data.Data_Transfer[248],0,8) MOV(Rules.Settings[r_dex1].Total_Bytes,Port_Data.Data_Transfer[249]) OTL(Port_Data.Port_Read.[Port]) OTL(Control.4) ,EQU(Rules.Settings[r_dex1].RW,1) OTL(Control.11) ];
   12: XIC(Control.4)XIO(Control.5)XIO(Port_Data.Port_Read.[Port])OTL(Port_Data.Port_Read.[Port]);
   13: XIC(Control.5)XIO(Control.9)MOV(Rules.Settings[r_dex1].Rules[r_dex2].Sub_Index,r_dex3)MOV(Rules.Settings[r_dex1].Rules[r_dex2].Byte_Pos,r_dex5)ADD(r_dex5,1,m1)ADD(r_dex5,2,m2)ADD(r_dex5,3,m3)OTL(Control.9);
   14: MOV(Rules.Settings[r_dex1].Rules[r_dex2].Multi,b_dex)MOV(Rules.Settings[r_dex1].Rules[r_dex2].Signed,s_dex);
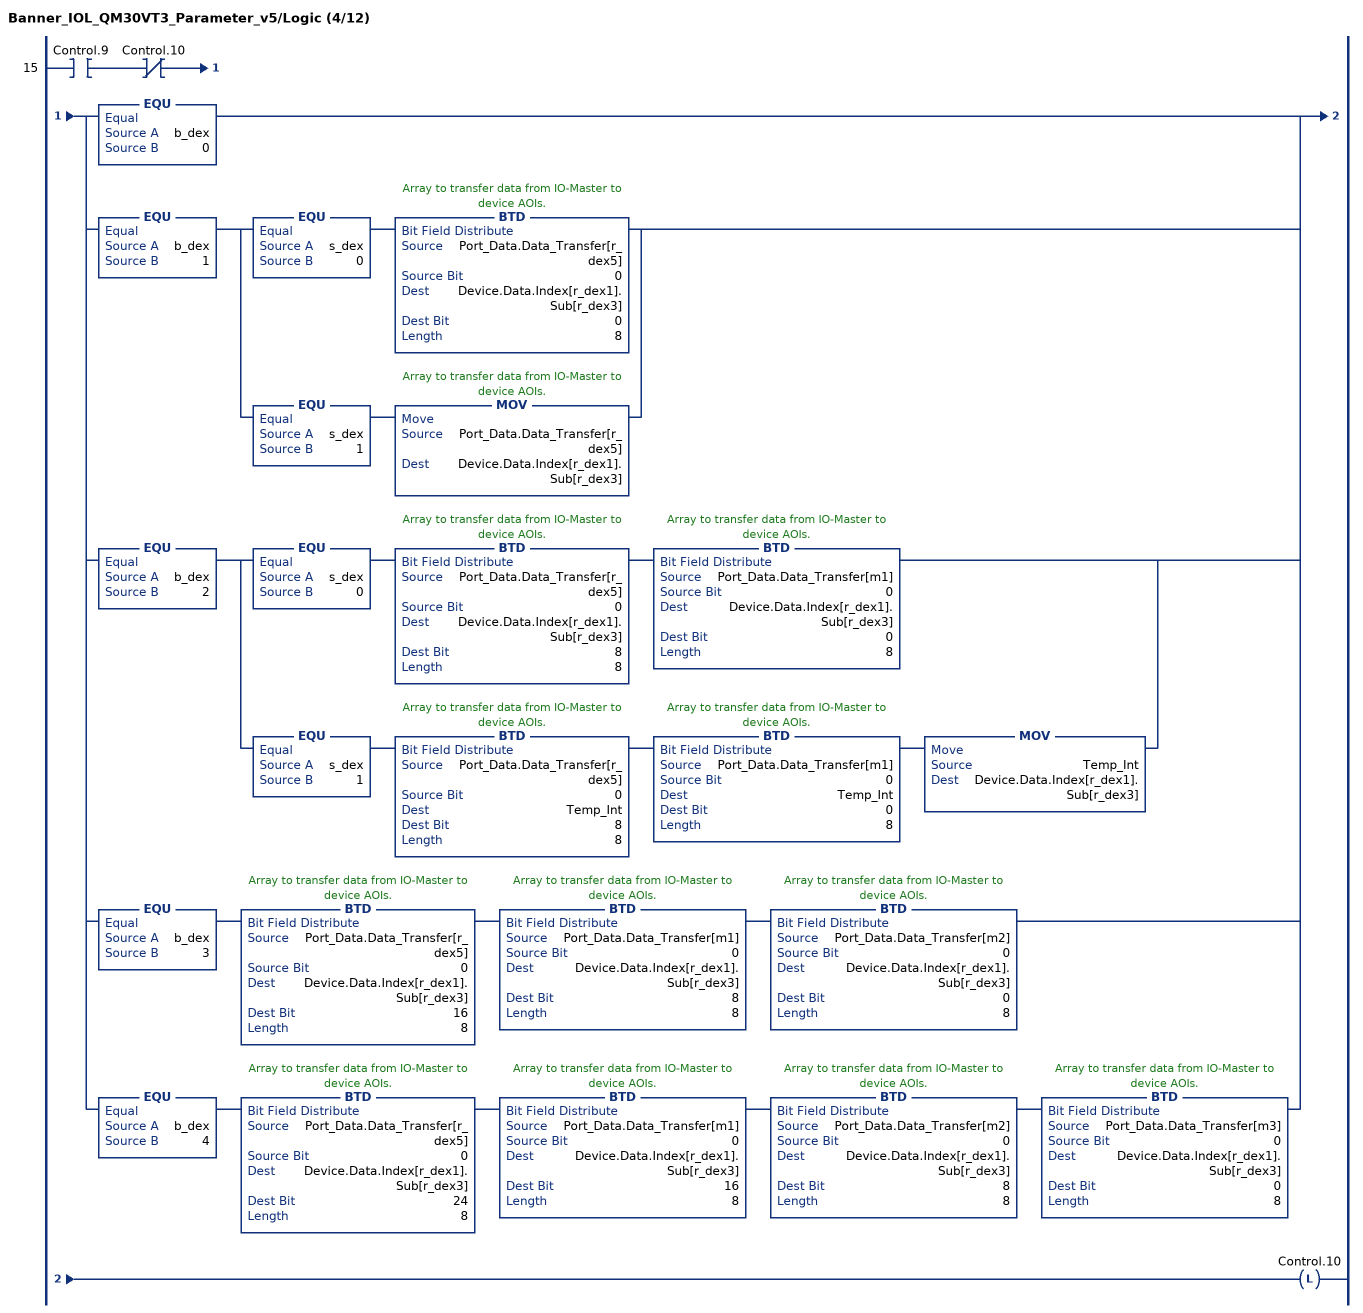
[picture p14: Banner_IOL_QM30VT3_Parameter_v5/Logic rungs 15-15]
   15: XIC(Control.9)XIO(Control.10)[EQU(b_dex,0) ,EQU(b_dex,1) [EQU(s_dex,0) BTD(Port_Data.Data_Transfer[r_dex5],0,Device.Data.Index[r_dex1].Sub[r_dex3],0,8) ,EQU(s_dex,1) MOV(Port_Data.Data_Transfer[r_dex5],Device.Data.Index[r_dex1].Sub[r_dex3]) ] ,EQU(b_dex,2) [EQU(s_dex,0) BTD(Port_Data.Data_Transfer[r_dex5],0,Device.Data.Index[r_dex1].Sub[r_dex3],8,8) BTD(Port_Data.Data_Transfer[m1],0,Device.Data.Index[r_dex1].Sub[r_dex3],0,8) ,EQU(s_dex,1) BTD(Port_Data.Data_Transfer[r_dex5],0,Temp_Int,8,8) BTD(Port_Data.Data_Transfer[m1],0,Temp_Int,0,8) MOV(Temp_Int,Device.Data.Index[r_dex1].Sub[r_dex3]) ] ,EQU(b_dex,3) BTD(Port_Data.Data_Transfer[r_dex5],0,Device.Data.Index[r_dex1].Sub[r_dex3],16,8) BTD(Port_Data.Data_Transfer[m1],0,Device.Data.Index[r_dex1].Sub[r_dex3],8,8) BTD(Port_Data.Data_Transfer[m2],0,Device.Data.Index[r_dex1].Sub[r_dex3],0,8) ,EQU(b_dex,4) BTD(Port_Data.Data_Transfer[r_dex5],0,Device.Data.Index[r_dex1].Sub[r_dex3],24,8) BTD(Port_Data.Data_Transfer[m1],0,Device.Data.Index[r_dex1].Sub[r_dex3],16,8) BTD(Port_Data.Data_Transfer[m2],0,Device.Data.Index[r_dex1].Sub[r_dex3],8,8) BTD(Port_Data.Data_Transfer[m3],0,Device.Data.Index[r_dex1].Sub[r_dex3],0,8) ]OTL(Control.10);
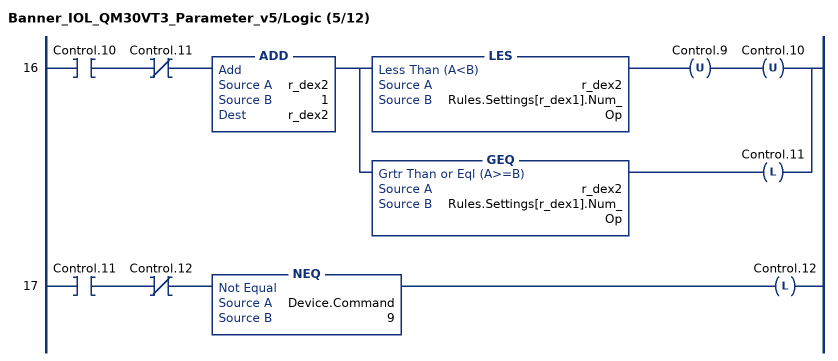
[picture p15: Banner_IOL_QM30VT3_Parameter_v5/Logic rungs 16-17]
   16: XIC(Control.10)XIO(Control.11)ADD(r_dex2,1,r_dex2)[LES(r_dex2,Rules.Settings[r_dex1].Num_Op) OTU(Control.9) OTU(Control.10) ,GEQ(r_dex2,Rules.Settings[r_dex1].Num_Op) OTL(Control.11) ];
   17: XIC(Control.11)XIO(Control.12)NEQ(Device.Command,9)OTL(Control.12);
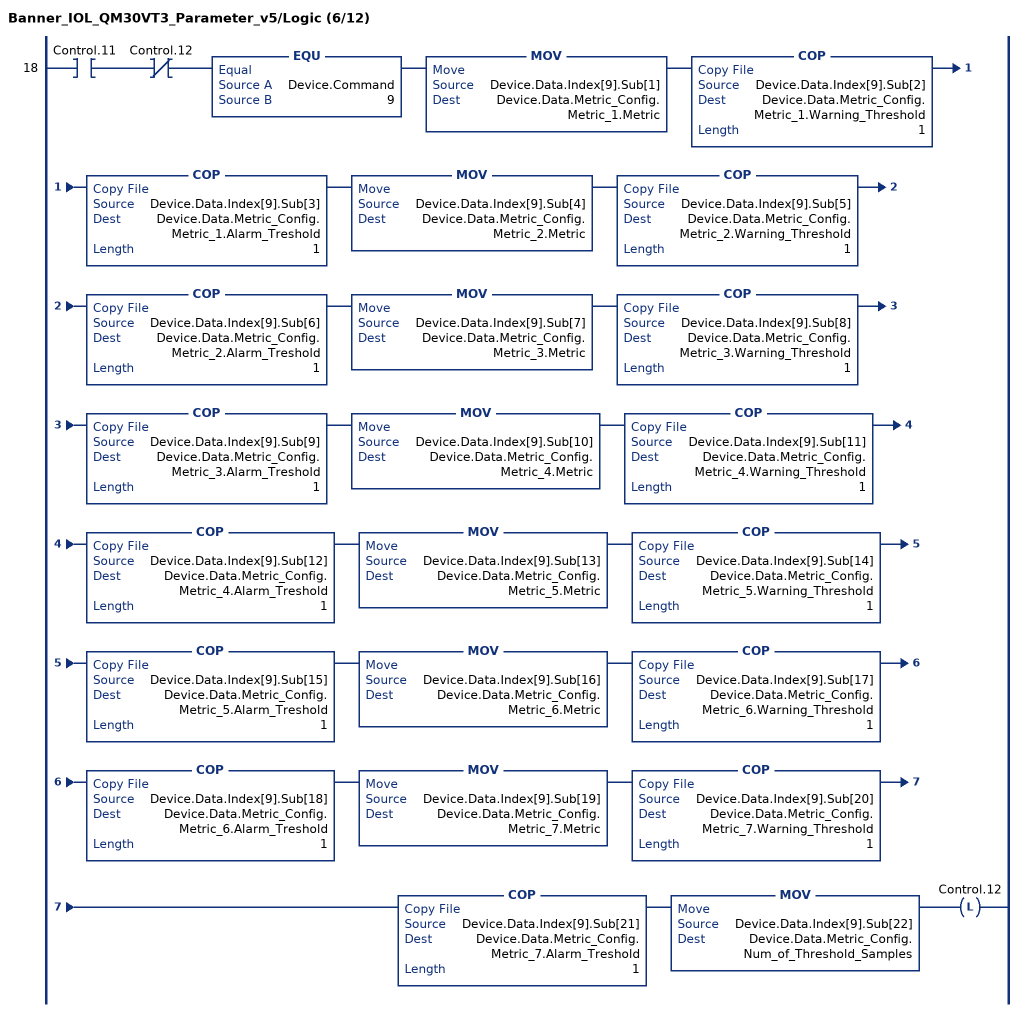
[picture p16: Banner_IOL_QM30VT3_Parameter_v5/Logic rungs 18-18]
   18: XIC(Control.11)XIO(Control.12)EQU(Device.Command,9)MOV(Device.Data.Index[9].Sub[1],Device.Data.Metric_Config.Metric_1.Metric)COP(Device.Data.Index[9].Sub[2],Device.Data.Metric_Config.Metric_1.Warning_Threshold,1)COP(Device.Data.Index[9].Sub[3],Device.Data.Metric_Config.Metric_1.Alarm_Treshold,1)MOV(Device.Data.Index[9].Sub[4],Device.Data.Metric_Config.Metric_2.Metric)COP(Device.Data.Index[9].Sub[5],Device.Data.Metric_Config.Metric_2.Warning_Threshold,1)COP(Device.Data.Index[9].Sub[6],Device.Data.Metric_Config.Metric_2.Alarm_Treshold,1)MOV(Device.Data.Index[9].Sub[7],Device.Data.Metric_Config.Metric_3.Metric)COP(Device.Data.Index[9].Sub[8],Device.Data.Metric_Config.Metric_3.Warning_Threshold,1)COP(Device.Data.Index[9].Sub[9],Device.Data.Metric_Config.Metric_3.Alarm_Treshold,1)MOV(Device.Data.Index[9].Sub[10],Device.Data.Metric_Config.Metric_4.Metric)COP(Device.Data.Index[9].Sub[11],Device.Data.Metric_Config.Metric_4.Warning_Threshold,1)COP(Device.Data.Index[9].Sub[12],Device.Data.Metric_Config.Metric_4.Alarm_Treshold,1)MOV(Device.Data.Index[9].Sub[13],Device.Data.Metric_Config.Metric_5.Metric)COP(Device.Data.Index[9].Sub[14],Device.Data.Metric_Config.Metric_5.Warning_Threshold,1)COP(Device.Data.Index[9].Sub[15],Device.Data.Metric_Config.Metric_5.Alarm_Treshold,1)MOV(Device.Data.Index[9].Sub[16],Device.Data.Metric_Config.Metric_6.Metric)COP(Device.Data.Index[9].Sub[17],Device.Data.Metric_Config.Metric_6.Warning_Threshold,1)COP(Device.Data.Index[9].Sub[18],Device.Data.Metric_Config.Metric_6.Alarm_Treshold,1)MOV(Device.Data.Index[9].Sub[19],Device.Data.Metric_Config.Metric_7.Metric)COP(Device.Data.Index[9].Sub[20],Device.Data.Metric_Config.Metric_7.Warning_Threshold,1)COP(Device.Data.Index[9].Sub[21],Device.Data.Metric_Config.Metric_7.Alarm_Treshold,1)MOV(Device.Data.Index[9].Sub[22],Device.Data.Metric_Config.Num_of_Threshold_Samples)OTL(Control.12);
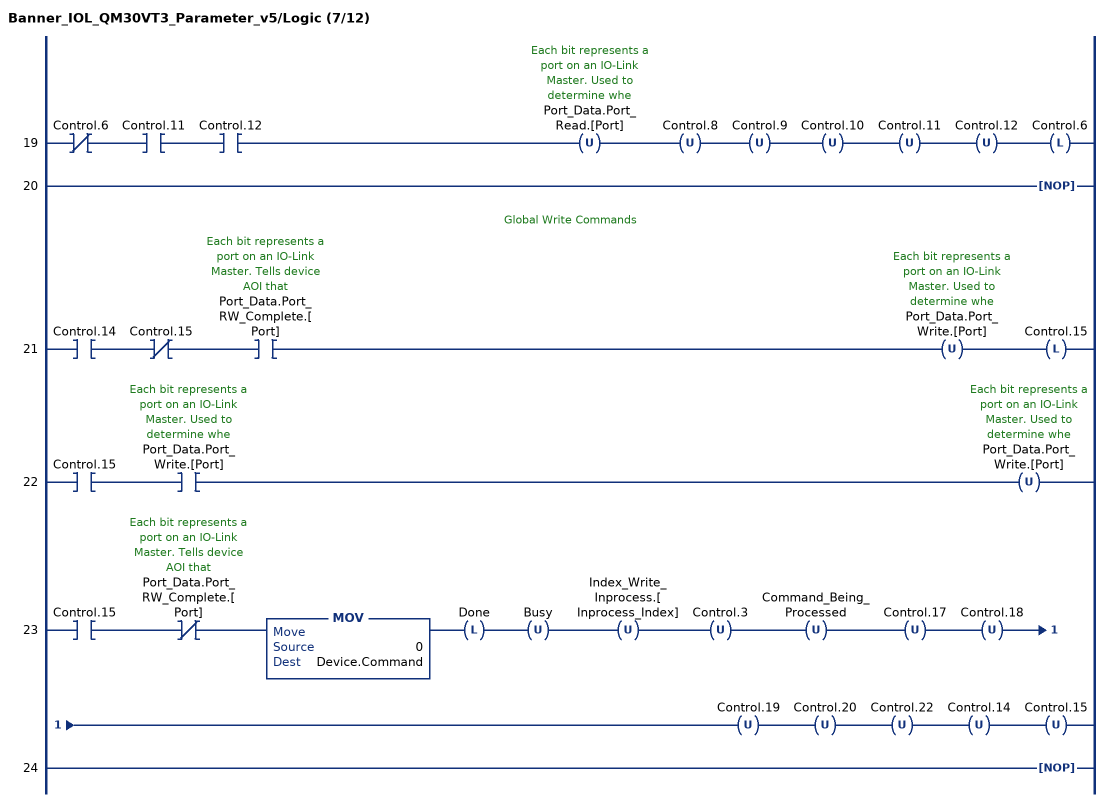
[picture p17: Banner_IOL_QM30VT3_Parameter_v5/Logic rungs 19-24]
   19: XIO(Control.6)XIC(Control.11)XIC(Control.12)OTU(Port_Data.Port_Read.[Port])OTU(Control.8)OTU(Control.9)OTU(Control.10)OTU(Control.11)OTU(Control.12)OTL(Control.6);
   20: NOP();
   // Global Write Commands
   21: XIC(Control.14)XIO(Control.15)XIC(Port_Data.Port_RW_Complete.[Port])OTU(Port_Data.Port_Write.[Port])OTL(Control.15);
   22: XIC(Control.15)XIC(Port_Data.Port_Write.[Port])OTU(Port_Data.Port_Write.[Port]);
   23: XIC(Control.15)XIO(Port_Data.Port_RW_Complete.[Port])MOV(0,Device.Command)OTL(Done)OTU(Busy)OTU(Index_Write_Inprocess.[Inprocess_Index])OTU(Control.3)OTU(Command_Being_Processed)OTU(Control.17)OTU(Control.18)OTU(Control.19)OTU(Control.20)OTU(Control.22)OTU(Control.14)OTU(Control.15);
   24: NOP();
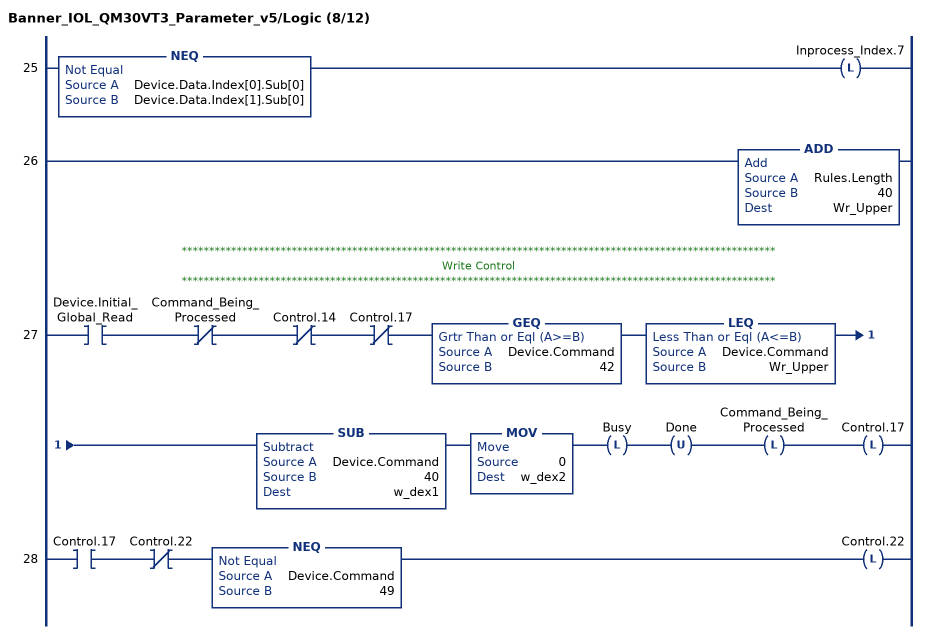
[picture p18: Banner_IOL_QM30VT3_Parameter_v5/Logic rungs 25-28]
   25: NEQ(Device.Data.Index[0].Sub[0],Device.Data.Index[1].Sub[0])OTL(Inprocess_Index.7);
   26: ADD(Rules.Length,40,Wr_Upper);
   // ************************************************************************************************************
   // Write Control
   // ************************************************************************************************************
   27: XIC(Device.Initial_Global_Read)XIO(Command_Being_Processed)XIO(Control.14)XIO(Control.17)GEQ(Device.Command,42)LEQ(Device.Command,Wr_Upper)SUB(Device.Command,40,w_dex1)MOV(0,w_dex2)OTL(Busy)OTU(Done)OTL(Command_Being_Processed)OTL(Control.17);
   28: XIC(Control.17)XIO(Control.22)NEQ(Device.Command,49)OTL(Control.22);
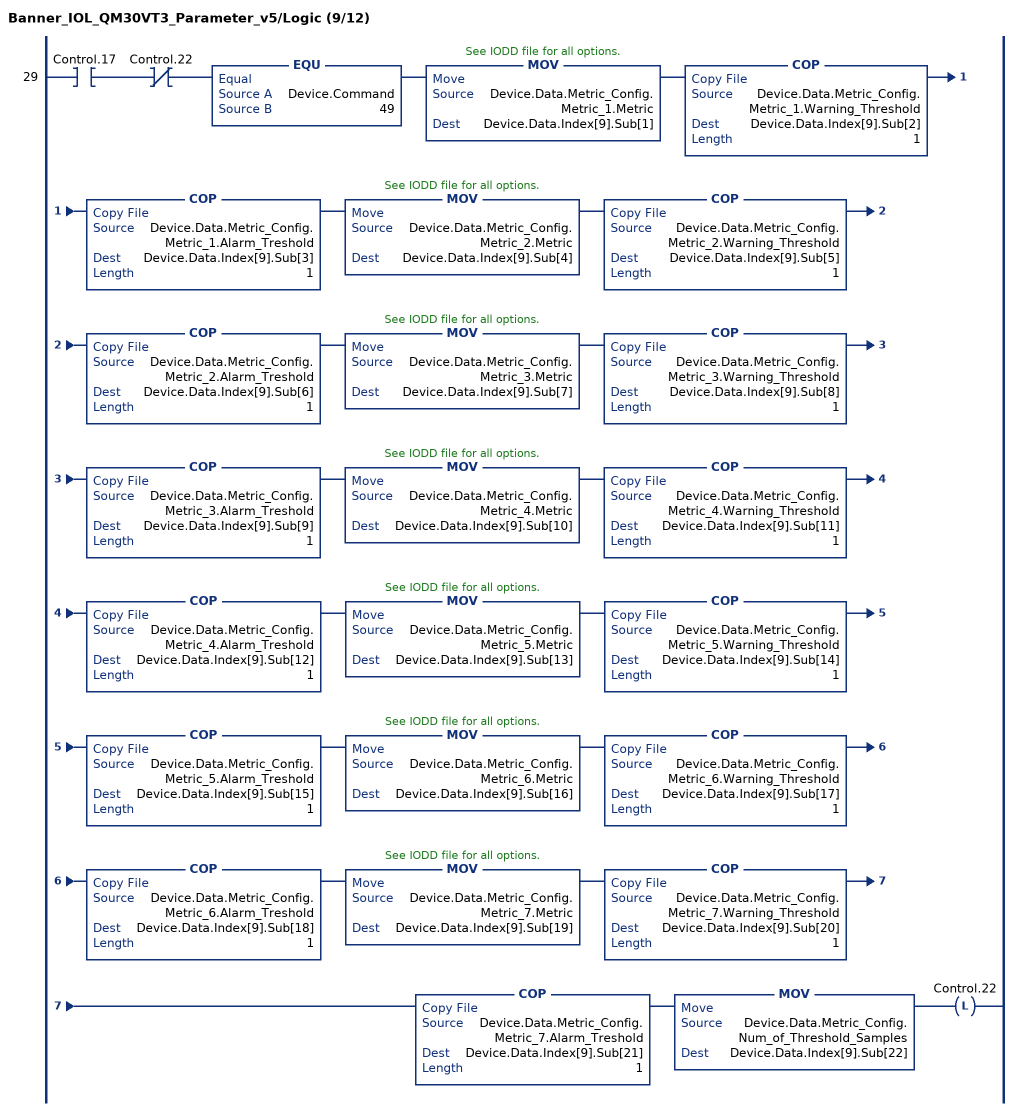
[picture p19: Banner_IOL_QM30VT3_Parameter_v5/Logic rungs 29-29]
   29: XIC(Control.17)XIO(Control.22)EQU(Device.Command,49)MOV(Device.Data.Metric_Config.Metric_1.Metric,Device.Data.Index[9].Sub[1])COP(Device.Data.Metric_Config.Metric_1.Warning_Threshold,Device.Data.Index[9].Sub[2],1)COP(Device.Data.Metric_Config.Metric_1.Alarm_Treshold,Device.Data.Index[9].Sub[3],1)MOV(Device.Data.Metric_Config.Metric_2.Metric,Device.Data.Index[9].Sub[4])COP(Device.Data.Metric_Config.Metric_2.Warning_Threshold,Device.Data.Index[9].Sub[5],1)COP(Device.Data.Metric_Config.Metric_2.Alarm_Treshold,Device.Data.Index[9].Sub[6],1)MOV(Device.Data.Metric_Config.Metric_3.Metric,Device.Data.Index[9].Sub[7])COP(Device.Data.Metric_Config.Metric_3.Warning_Threshold,Device.Data.Index[9].Sub[8],1)COP(Device.Data.Metric_Config.Metric_3.Alarm_Treshold,Device.Data.Index[9].Sub[9],1)MOV(Device.Data.Metric_Config.Metric_4.Metric,Device.Data.Index[9].Sub[10])COP(Device.Data.Metric_Config.Metric_4.Warning_Threshold,Device.Data.Index[9].Sub[11],1)COP(Device.Data.Metric_Config.Metric_4.Alarm_Treshold,Device.Data.Index[9].Sub[12],1)MOV(Device.Data.Metric_Config.Metric_5.Metric,Device.Data.Index[9].Sub[13])COP(Device.Data.Metric_Config.Metric_5.Warning_Threshold,Device.Data.Index[9].Sub[14],1)COP(Device.Data.Metric_Config.Metric_5.Alarm_Treshold,Device.Data.Index[9].Sub[15],1)MOV(Device.Data.Metric_Config.Metric_6.Metric,Device.Data.Index[9].Sub[16])COP(Device.Data.Metric_Config.Metric_6.Warning_Threshold,Device.Data.Index[9].Sub[17],1)COP(Device.Data.Metric_Config.Metric_6.Alarm_Treshold,Device.Data.Index[9].Sub[18],1)MOV(Device.Data.Metric_Config.Metric_7.Metric,Device.Data.Index[9].Sub[19])COP(Device.Data.Metric_Config.Metric_7.Warning_Threshold,Device.Data.Index[9].Sub[20],1)COP(Device.Data.Metric_Config.Metric_7.Alarm_Treshold,Device.Data.Index[9].Sub[21],1)MOV(Device.Data.Metric_Config.Num_of_Threshold_Samples,Device.Data.Index[9].Sub[22])OTL(Control.22);
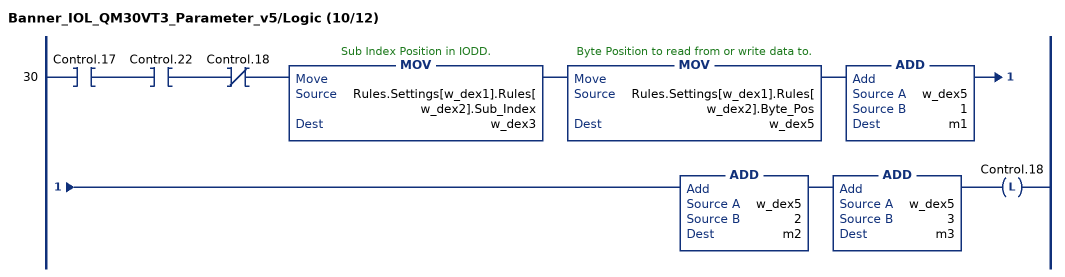
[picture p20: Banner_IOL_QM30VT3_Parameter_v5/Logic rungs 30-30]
   30: XIC(Control.17)XIC(Control.22)XIO(Control.18)MOV(Rules.Settings[w_dex1].Rules[w_dex2].Sub_Index,w_dex3)MOV(Rules.Settings[w_dex1].Rules[w_dex2].Byte_Pos,w_dex5)ADD(w_dex5,1,m1)ADD(w_dex5,2,m2)ADD(w_dex5,3,m3)OTL(Control.18);
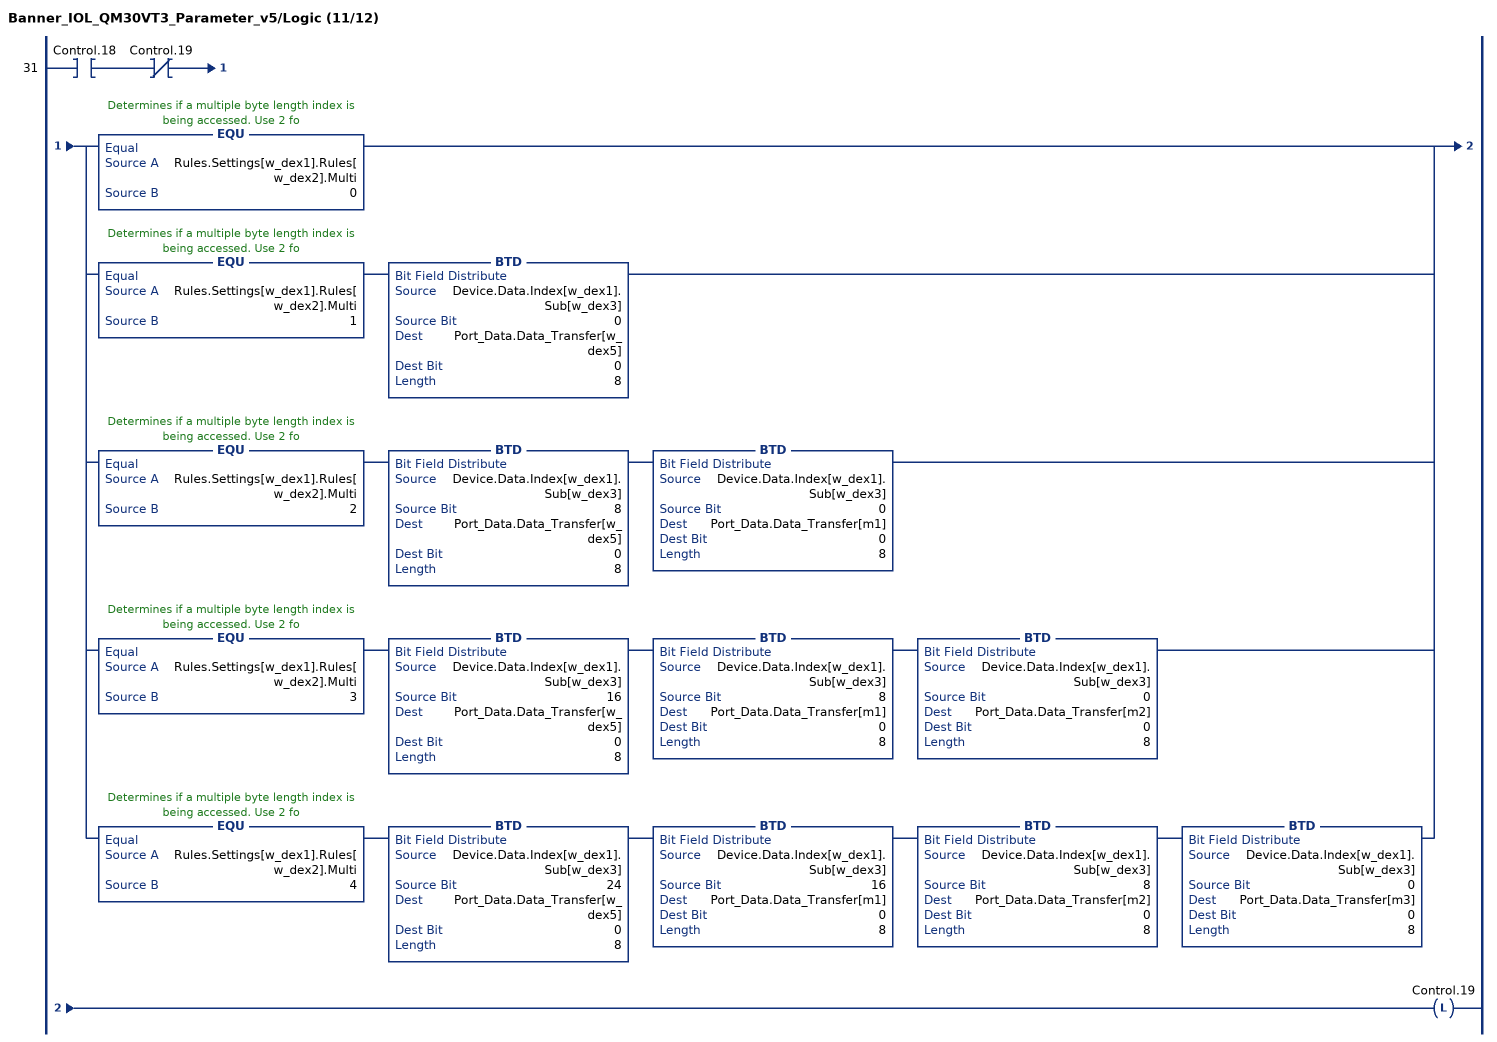
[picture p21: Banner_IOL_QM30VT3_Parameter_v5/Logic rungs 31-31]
   31: XIC(Control.18)XIO(Control.19)[EQU(Rules.Settings[w_dex1].Rules[w_dex2].Multi,0) ,EQU(Rules.Settings[w_dex1].Rules[w_dex2].Multi,1) BTD(Device.Data.Index[w_dex1].Sub[w_dex3],0,Port_Data.Data_Transfer[w_dex5],0,8) ,EQU(Rules.Settings[w_dex1].Rules[w_dex2].Multi,2) BTD(Device.Data.Index[w_dex1].Sub[w_dex3],8,Port_Data.Data_Transfer[w_dex5],0,8) BTD(Device.Data.Index[w_dex1].Sub[w_dex3],0,Port_Data.Data_Transfer[m1],0,8) ,EQU(Rules.Settings[w_dex1].Rules[w_dex2].Multi,3) BTD(Device.Data.Index[w_dex1].Sub[w_dex3],16,Port_Data.Data_Transfer[w_dex5],0,8) BTD(Device.Data.Index[w_dex1].Sub[w_dex3],8,Port_Data.Data_Transfer[m1],0,8) BTD(Device.Data.Index[w_dex1].Sub[w_dex3],0,Port_Data.Data_Transfer[m2],0,8) ,EQU(Rules.Settings[w_dex1].Rules[w_dex2].Multi,4) BTD(Device.Data.Index[w_dex1].Sub[w_dex3],24,Port_Data.Data_Transfer[w_dex5],0,8) BTD(Device.Data.Index[w_dex1].Sub[w_dex3],16,Port_Data.Data_Transfer[m1],0,8) BTD(Device.Data.Index[w_dex1].Sub[w_dex3],8,Port_Data.Data_Transfer[m2],0,8) BTD(Device.Data.Index[w_dex1].Sub[w_dex3],0,Port_Data.Data_Transfer[m3],0,8) ]OTL(Control.19);
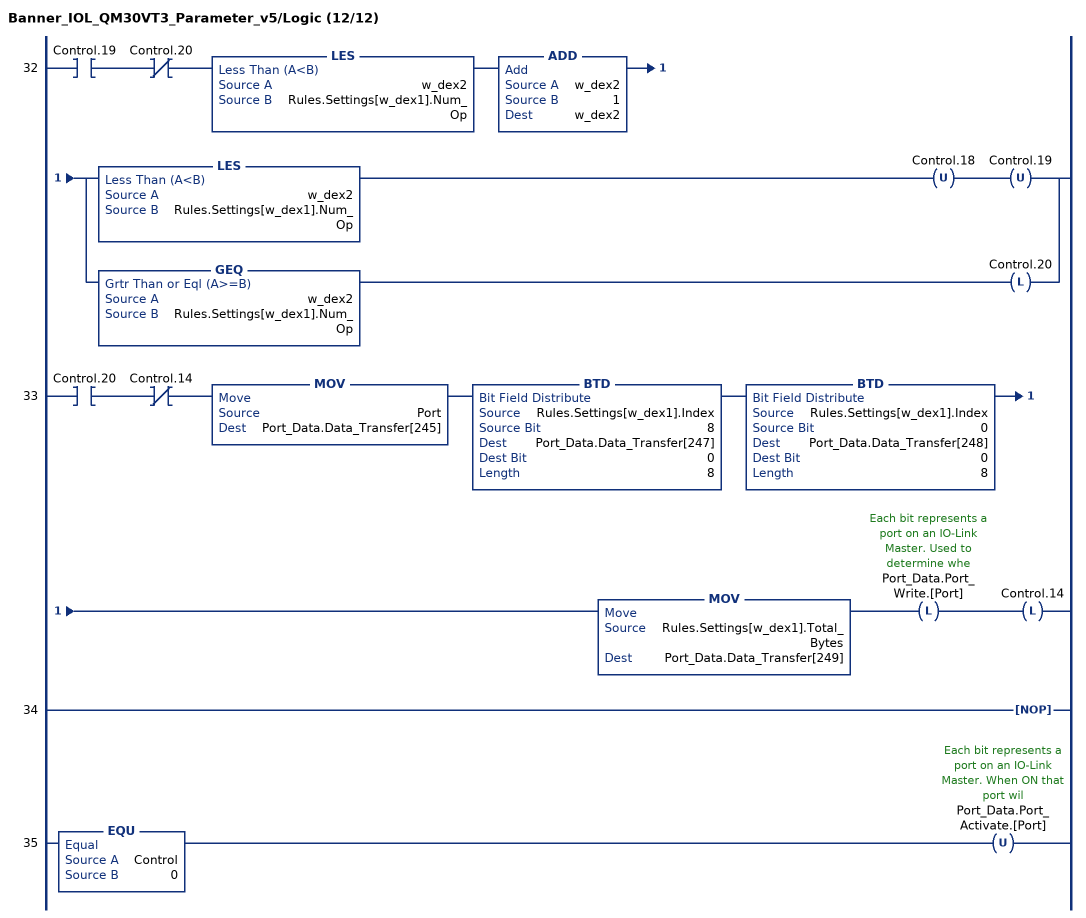
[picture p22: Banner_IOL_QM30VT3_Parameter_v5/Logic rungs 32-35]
   32: XIC(Control.19)XIO(Control.20)LES(w_dex2,Rules.Settings[w_dex1].Num_Op)ADD(w_dex2,1,w_dex2)[LES(w_dex2,Rules.Settings[w_dex1].Num_Op) OTU(Control.18) OTU(Control.19) ,GEQ(w_dex2,Rules.Settings[w_dex1].Num_Op) OTL(Control.20) ];
   33: XIC(Control.20)XIO(Control.14)MOV(Port,Port_Data.Data_Transfer[245])BTD(Rules.Settings[w_dex1].Index,8,Port_Data.Data_Transfer[247],0,8)BTD(Rules.Settings[w_dex1].Index,0,Port_Data.Data_Transfer[248],0,8)MOV(Rules.Settings[w_dex1].Total_Bytes,Port_Data.Data_Transfer[249])OTL(Port_Data.Port_Write.[Port])OTL(Control.14);
   34: NOP();
   35: EQU(Control,0)OTU(Port_Data.Port_Activate.[Port]);
END_ROUTINE
END_ADD_ON_INSTRUCTION
